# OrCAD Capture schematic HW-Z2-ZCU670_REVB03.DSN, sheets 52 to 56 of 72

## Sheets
52 052 VCC1V8 8A Reg: size Custom
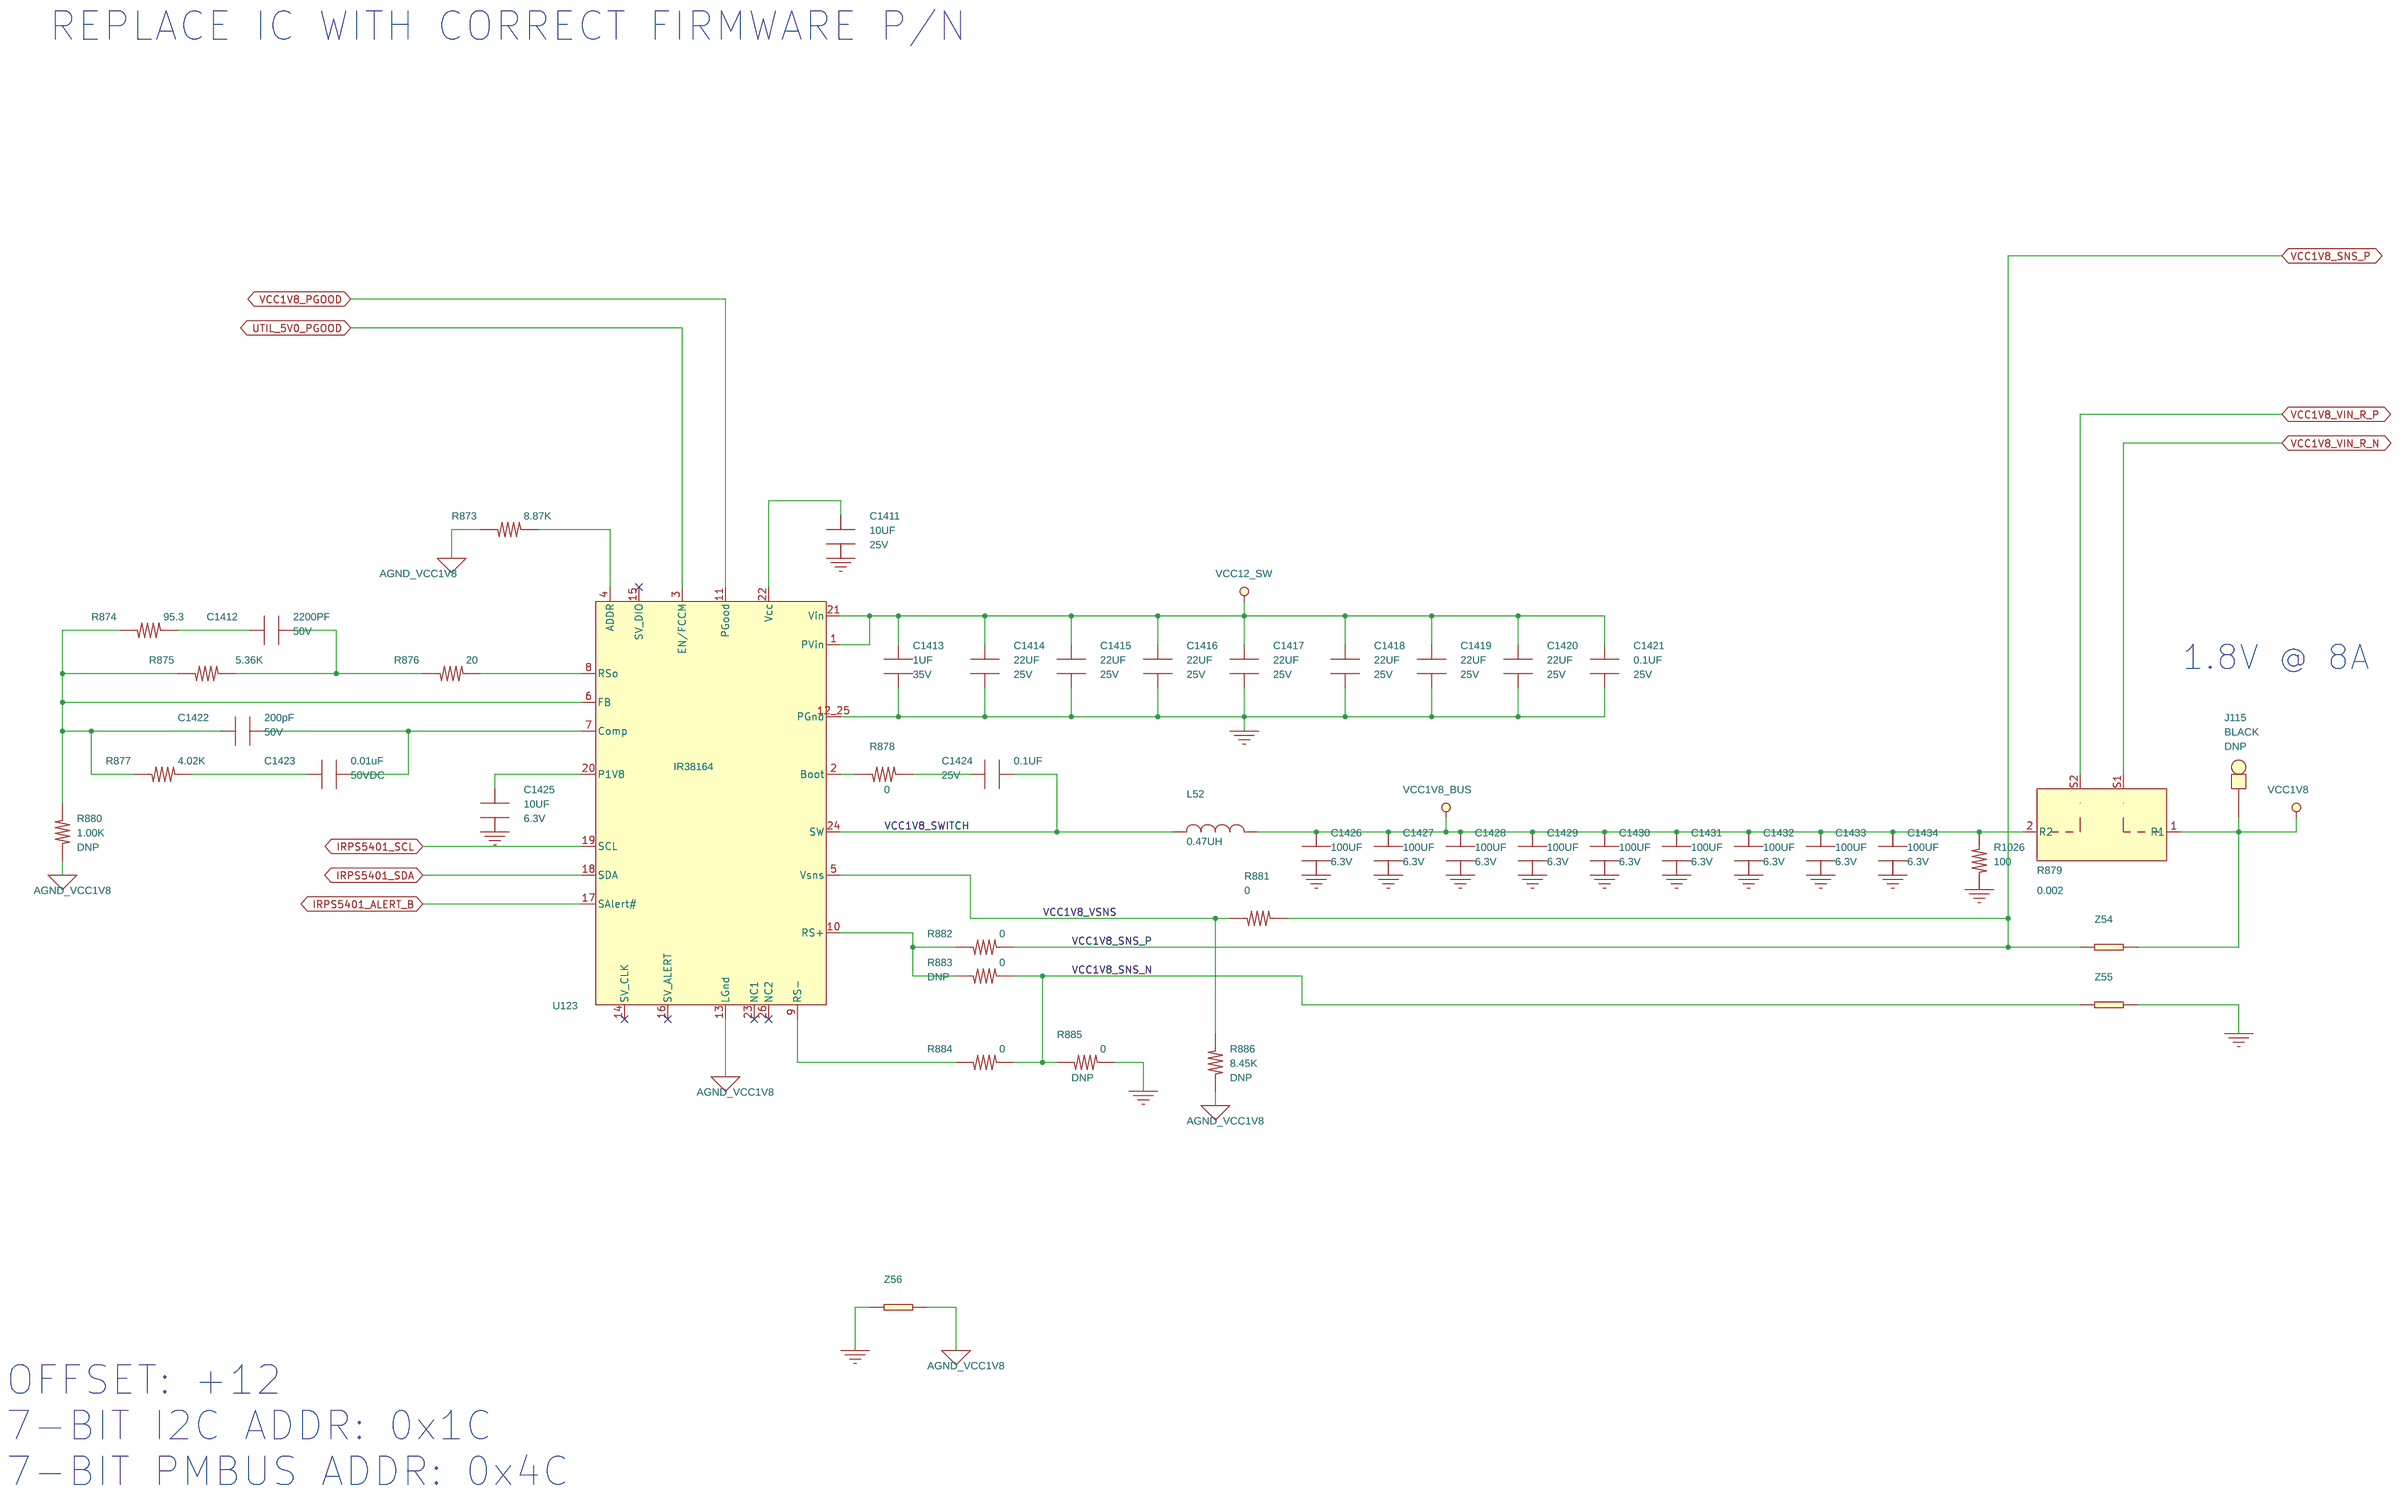
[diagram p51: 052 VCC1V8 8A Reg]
53 053 ADC_AVCC DAC_AVCC Reglators: size Custom
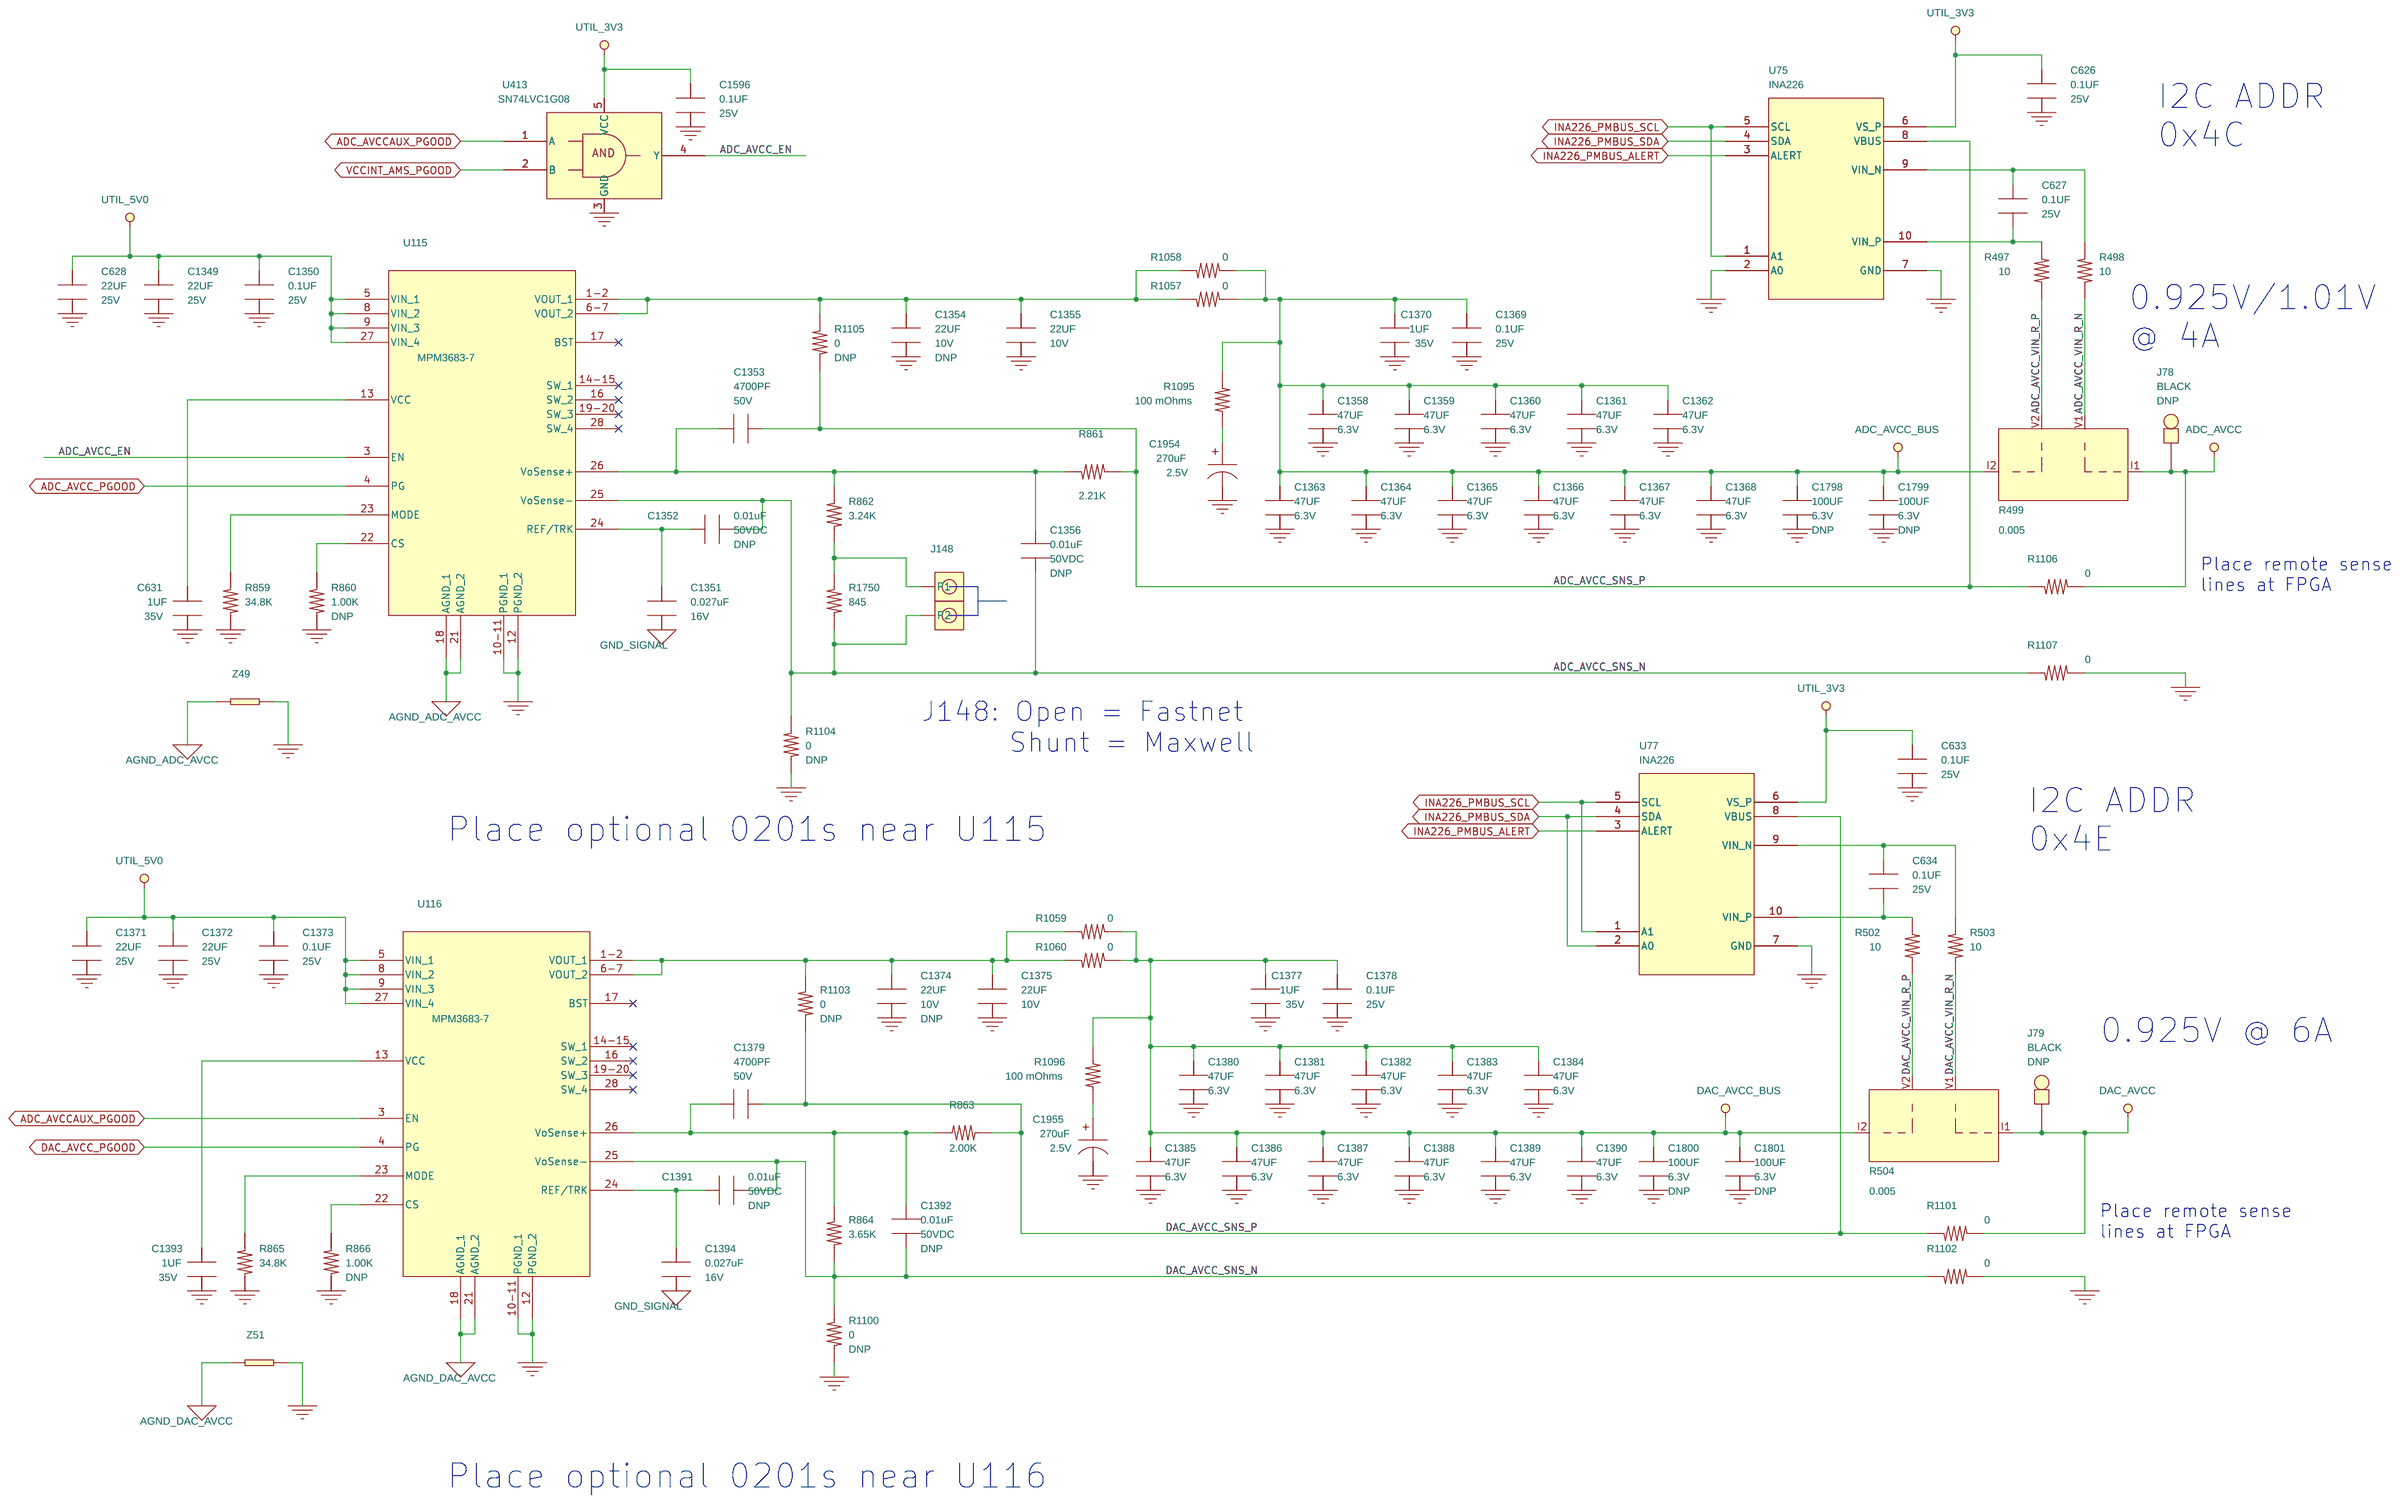
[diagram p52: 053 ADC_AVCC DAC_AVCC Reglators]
54 054 ADC_AVCCAUX 2A Regulator: size Custom
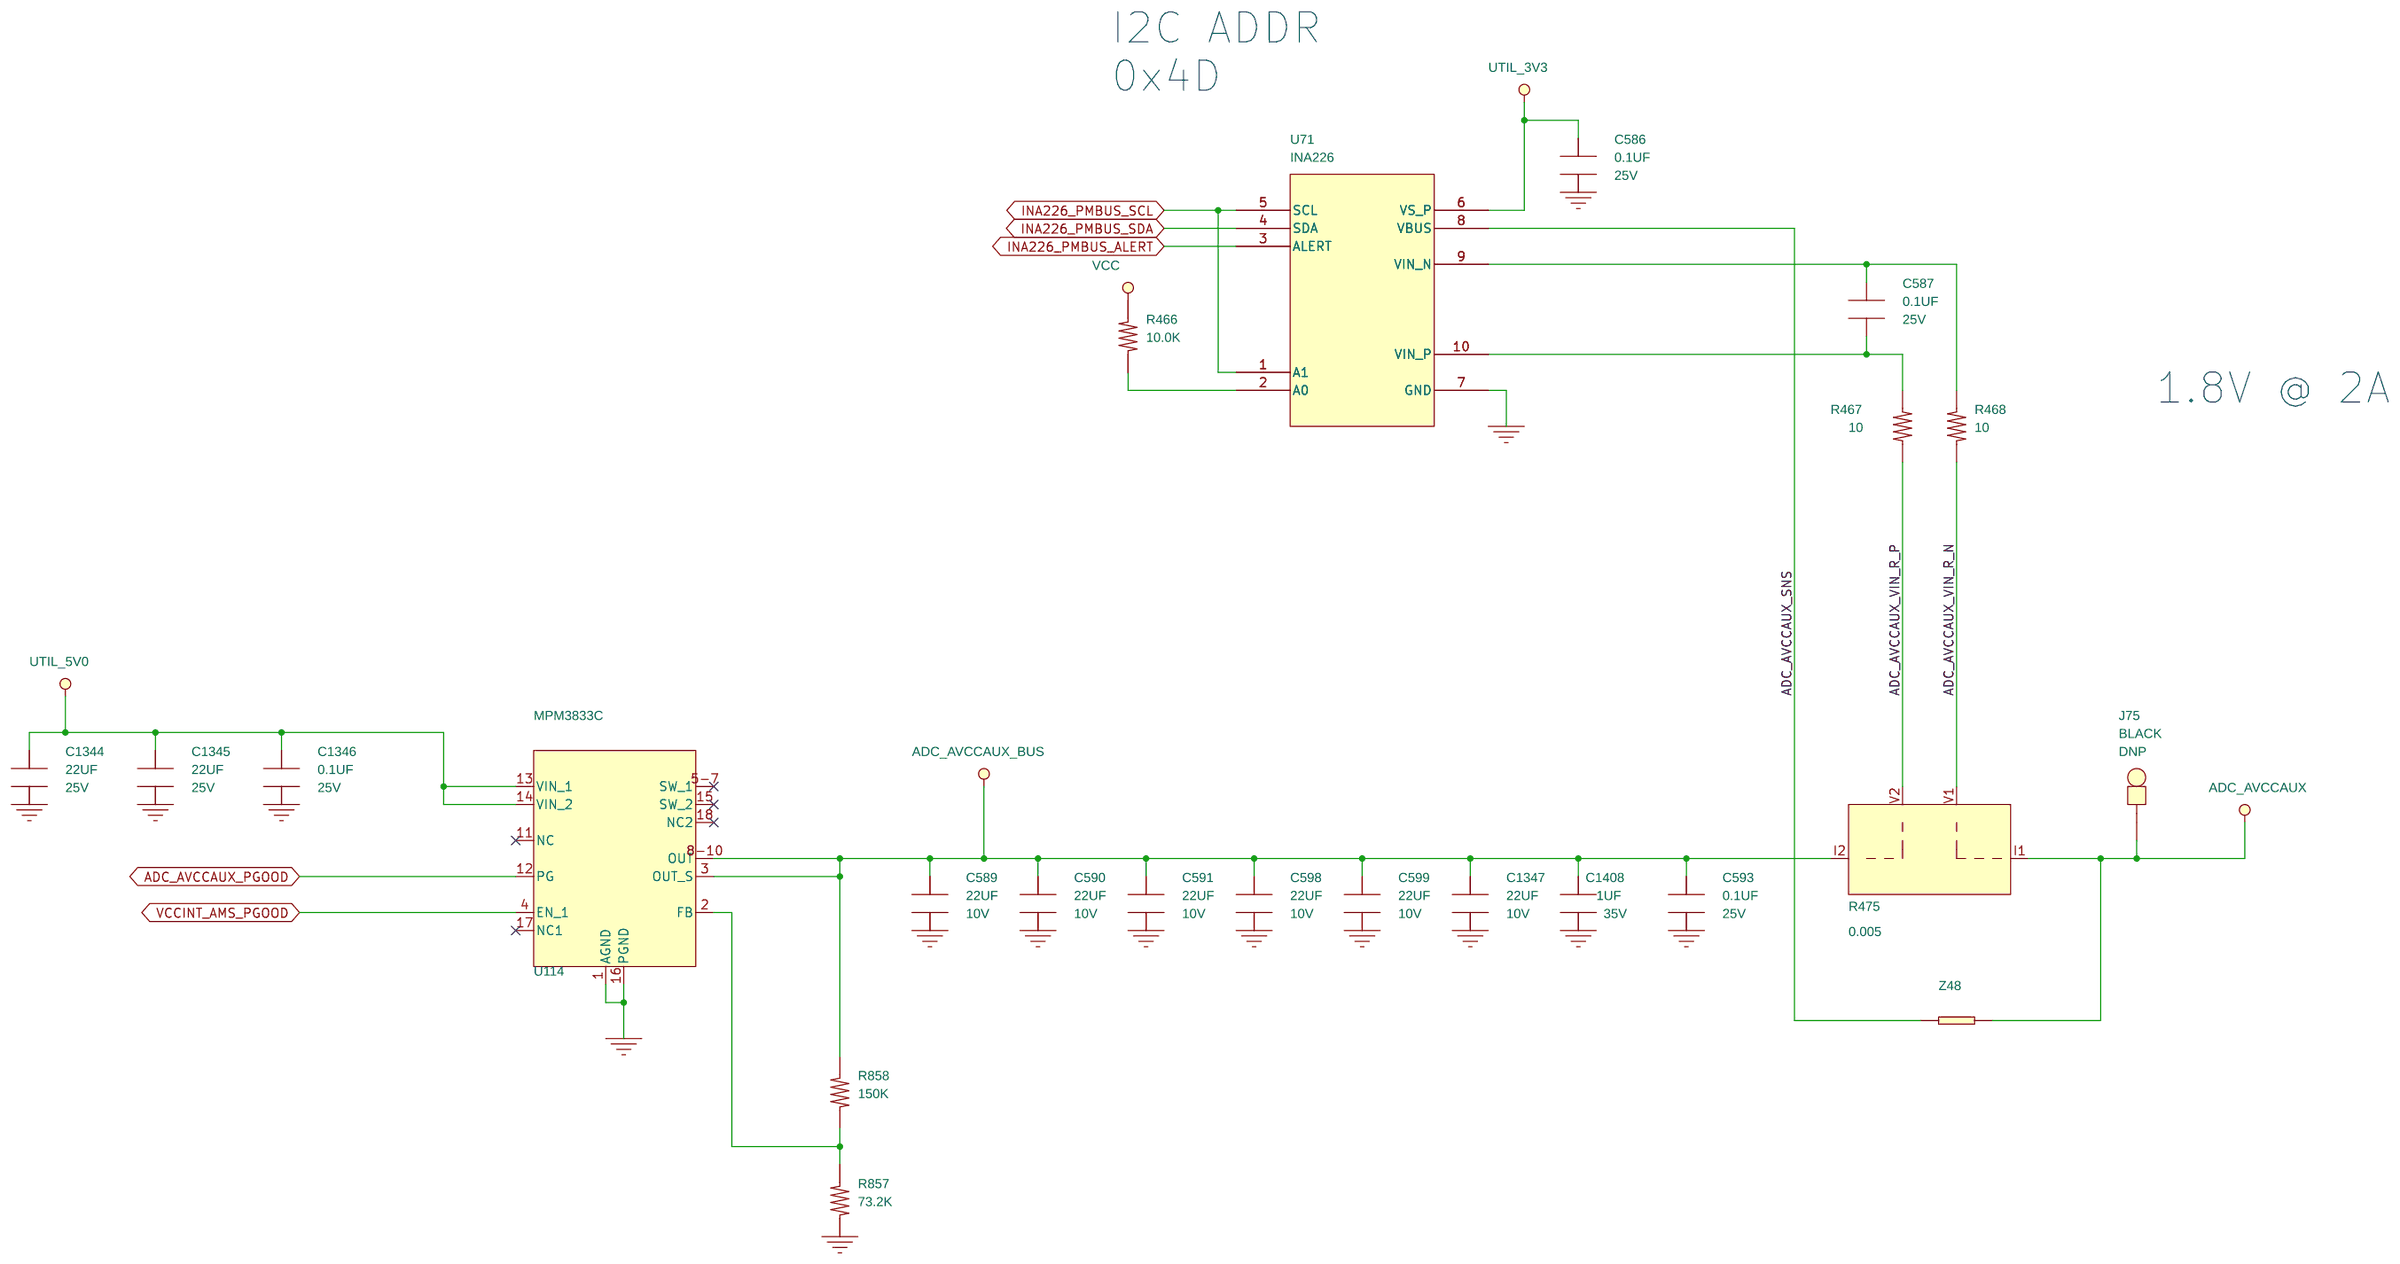
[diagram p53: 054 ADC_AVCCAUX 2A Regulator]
55 055 DAC_AVCCAUX DAC_AVTT Regs: size Custom
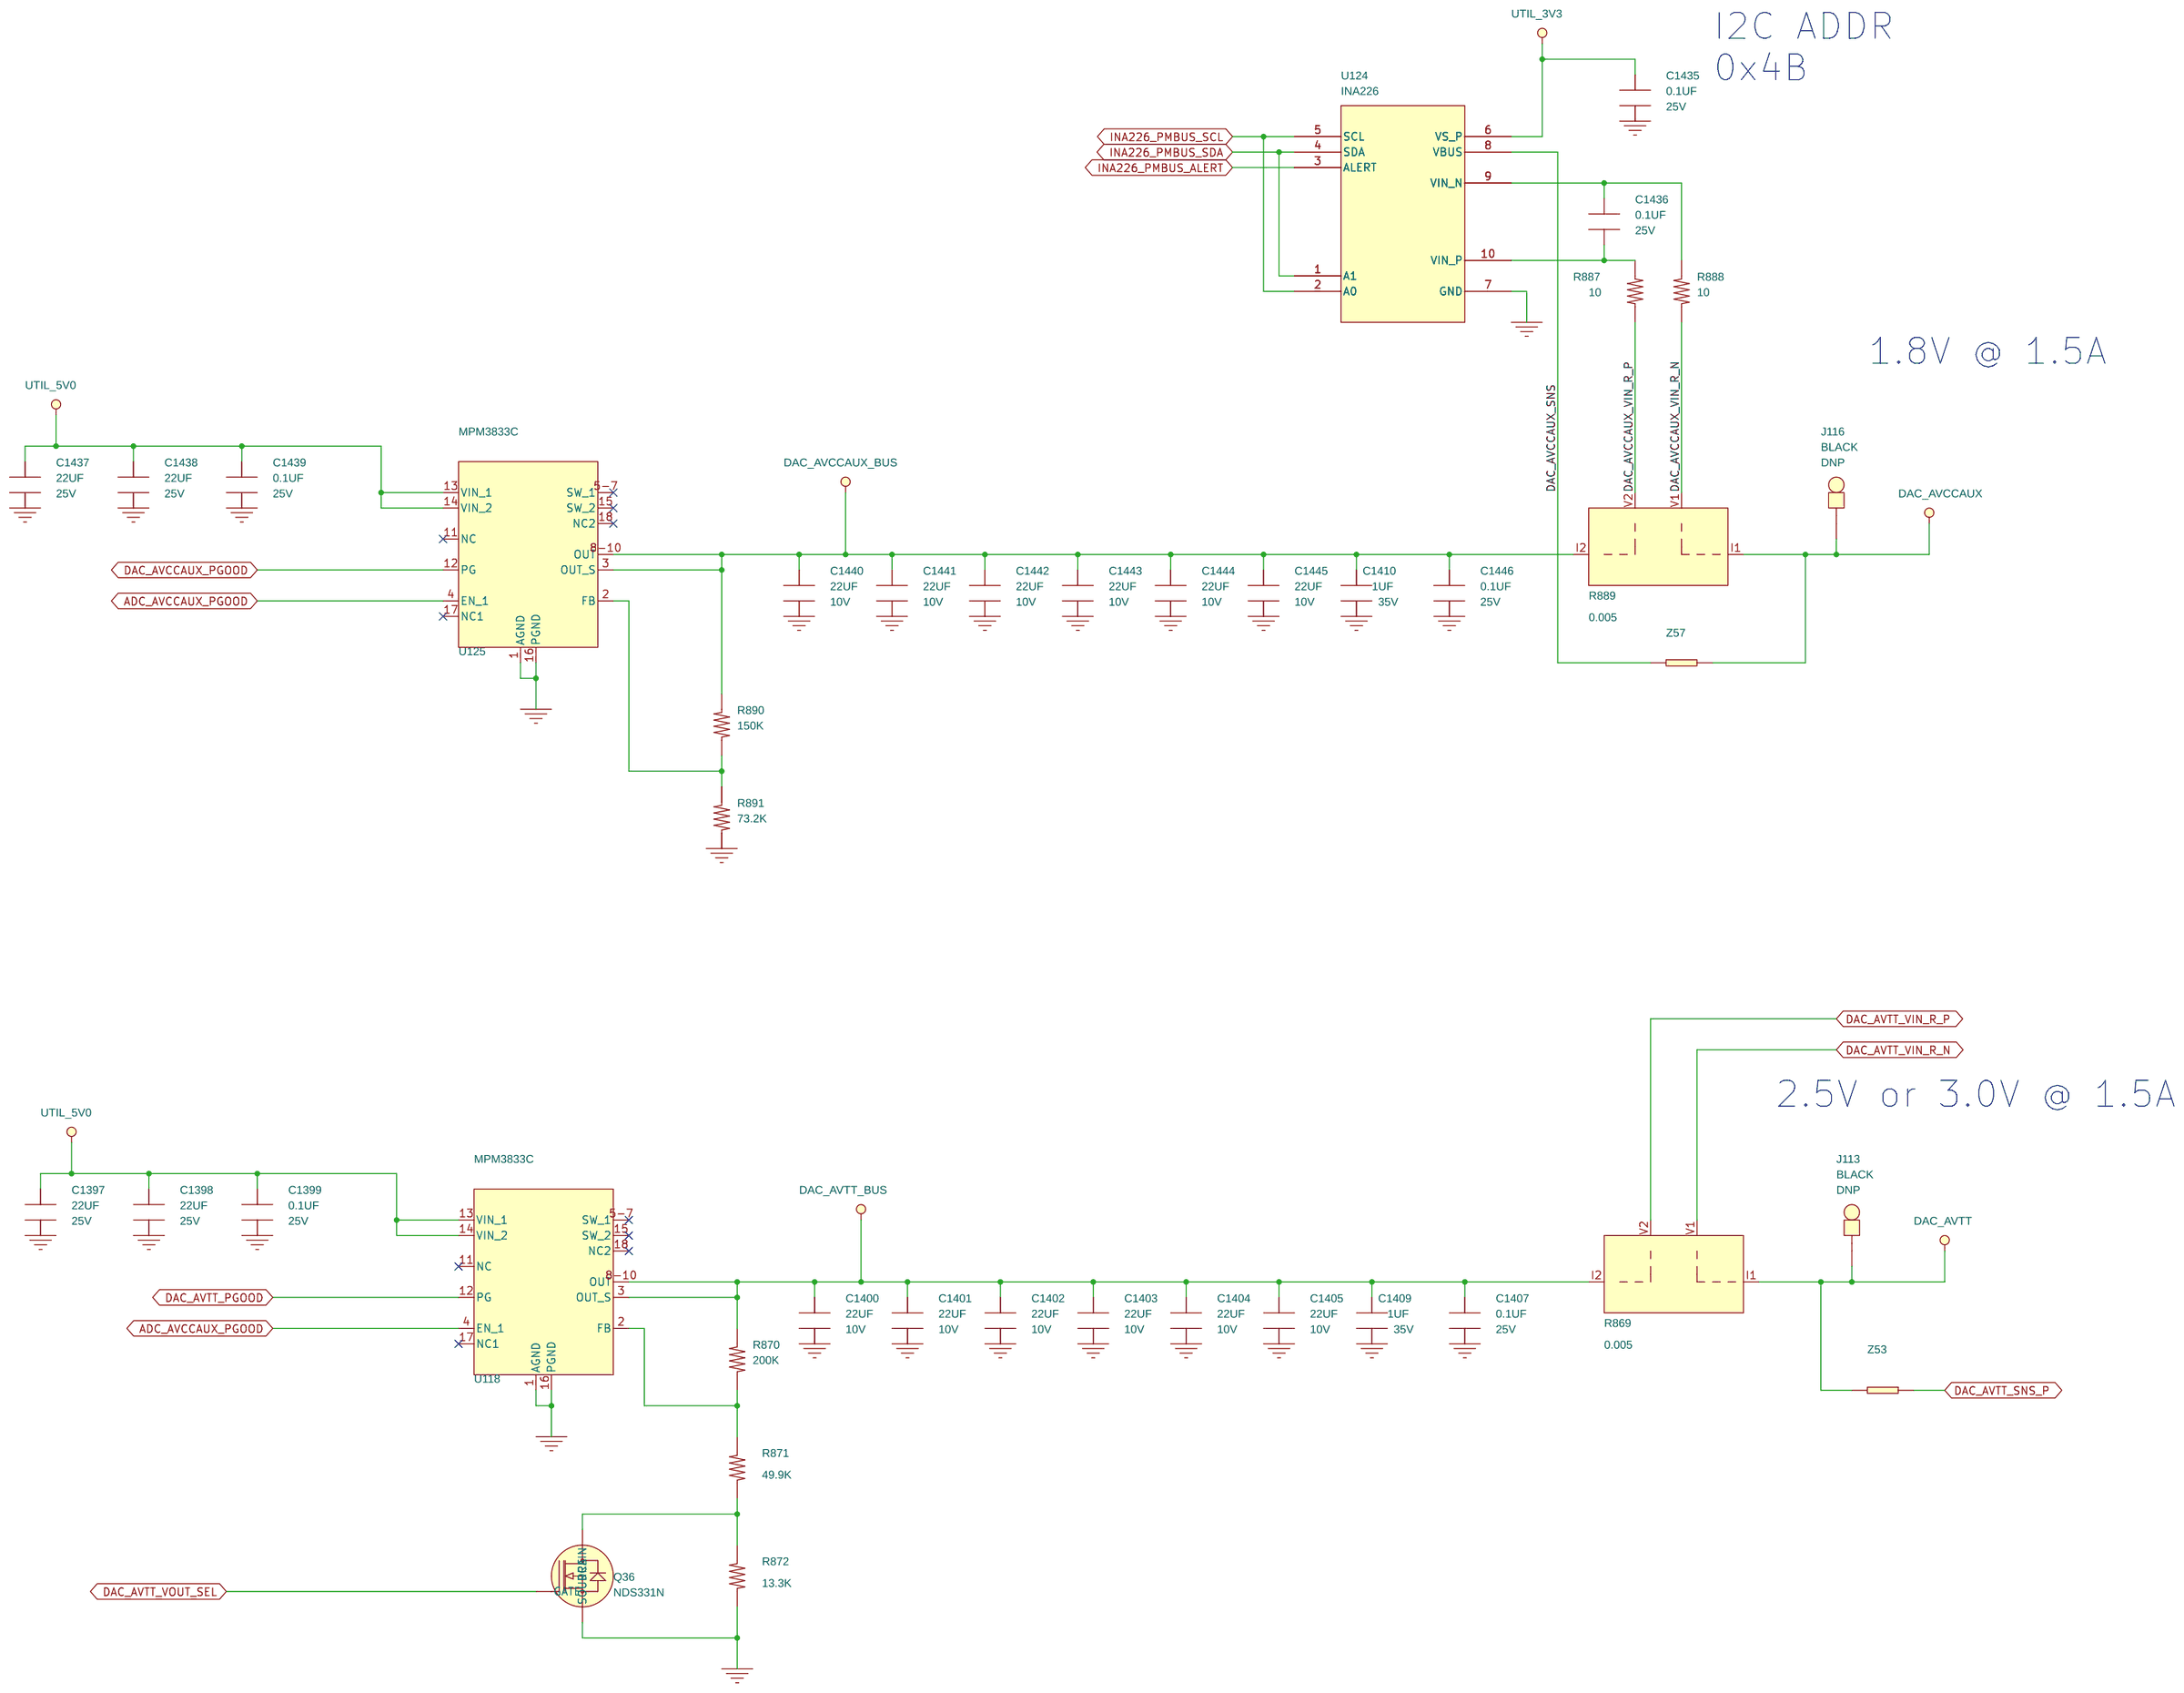
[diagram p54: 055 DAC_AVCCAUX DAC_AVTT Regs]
56 056 PMIC Current Sense: size Custom
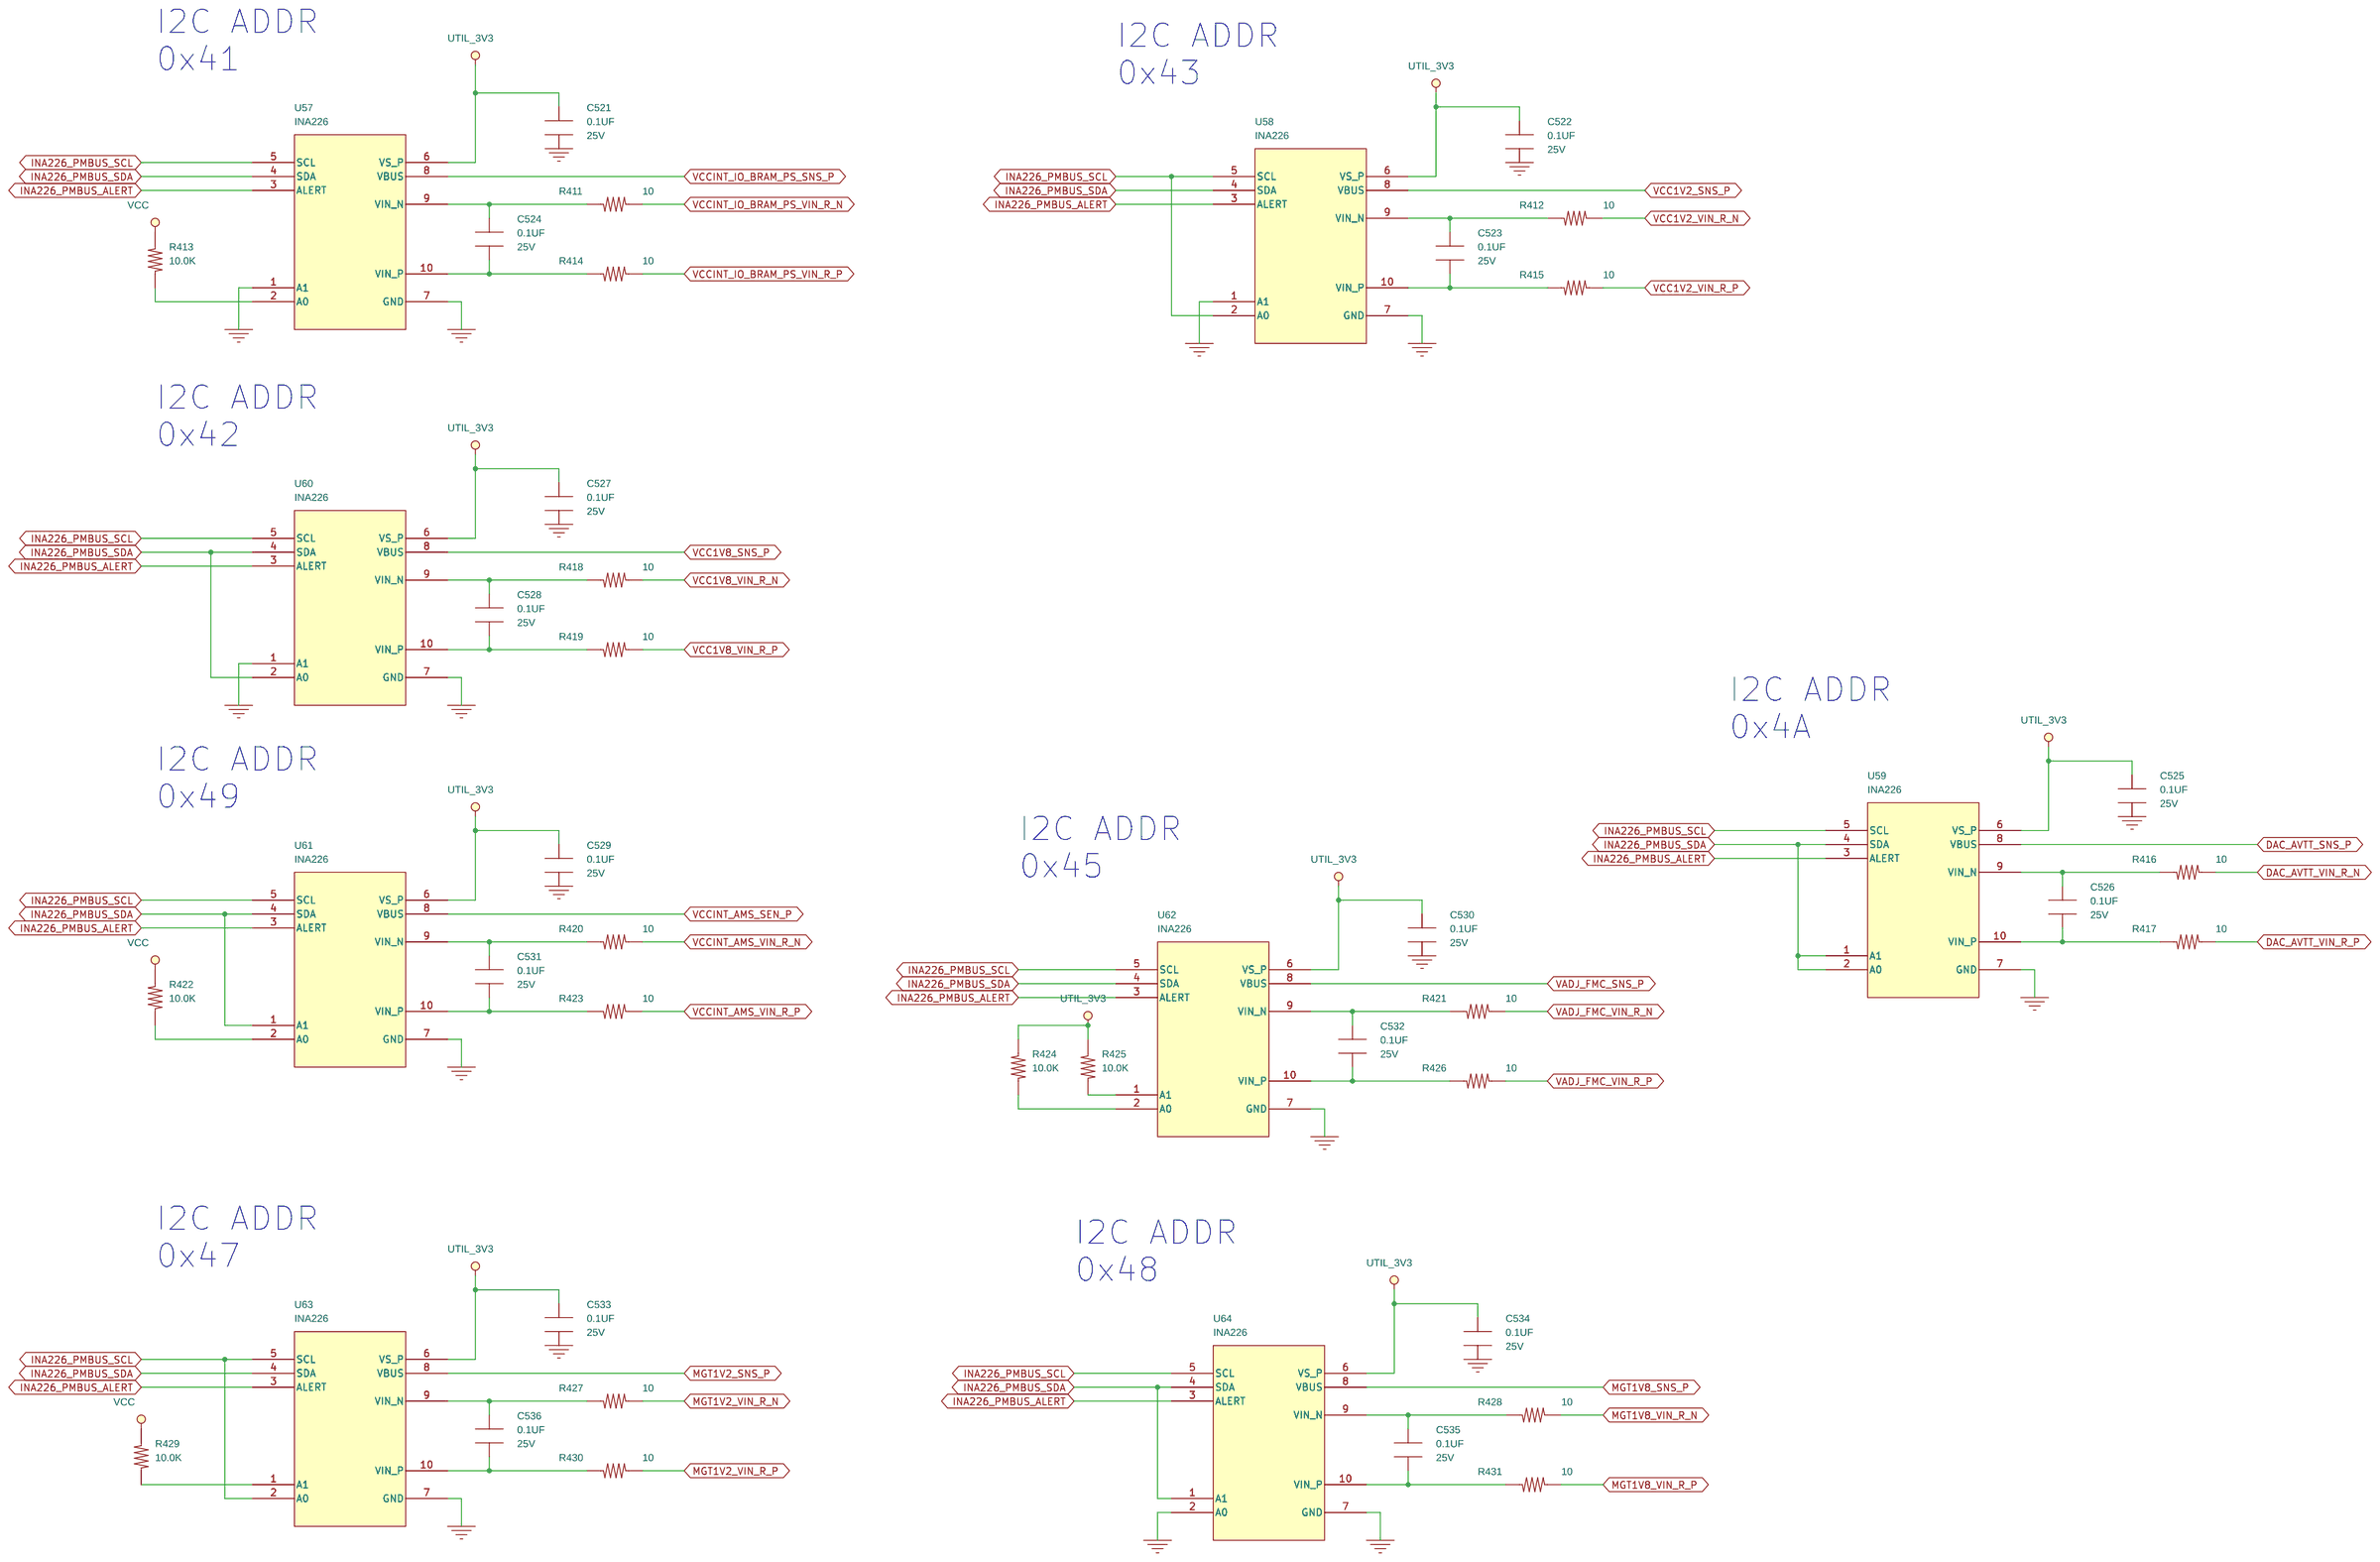
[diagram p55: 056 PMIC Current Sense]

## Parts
sheet 052 VCC1V8 8A Reg
C1411  10UF  [CAPC320X250X220]
C1412  2200PF  [CAPC100X50X55]
C1413  1UF  [CAPC100X50X60]
C1414  22UF  [CAPC320X160X180]
C1415  22UF  [CAPC320X160X180]
C1416  22UF  [CAPC320X160X180]
C1417  22UF  [CAPC320X160X180]
C1418  22UF  [CAPC320X160X180]
C1419  22UF  [CAPC320X160X180]
C1420  22UF  [CAPC320X160X180]
C1421  0.1UF  [CAPC100X50X55]
C1422  200pF  [CAPC100X50X55]
C1423  0.01uF  [CAPC100X50X55]
C1424  0.1UF  [CAPC100X50X55]
C1425  10UF  [CAPC100X50X70]
C1426  100UF  [CAPC320X160X180]
C1427  100UF  [CAPC320X160X180]
C1428  100UF  [CAPC320X160X180]
C1429  100UF  [CAPC320X160X180]
C1430  100UF  [CAPC320X160X180]
C1431  100UF  [CAPC320X160X180]
C1432  100UF  [CAPC320X160X180]
C1433  100UF  [CAPC320X160X180]
C1434  100UF  [CAPC320X160X180]
J115  BLACK  [TP_KEY_MINI]
L52  0.47UH  [INDM6864X300N]
R873  8.87K  [RESC100X50X40]
R874  95.3  [RESC100X50X40]
R875  5.36K  [RESC100X50X40]
R876  20  [RESC100X50X40]
R877  4.02K  [RESC100X50X40]
R878  0  [RESC100X50X40]
R879  0.002  [RES_WSL3637]
R880  1.00K  [RESC100X50X40]
R881  0  [RESC100X50X40]
R882  0  [RESC100X50X40]
R883  0  [RESC100X50X40]
R884  0  [RESC100X50X40]
R885  0  [RESC100X50X40]
R886  8.45K  [RESC100X50X40]
R1026  100  [RESC100X50X40]
U123  IR38164  [QFN_IR38164_26]
Z54  0201_SHORT  [0201_SHORT]
Z55  0201_SHORT  [0201_SHORT]
Z56  0201_SHORT  [0201_SHORT]
sheet 053 ADC_AVCC DAC_AVCC Reglators
C626  0.1UF  [CAPC100X50X55]
C627  0.1UF  [CAPC100X50X55]
C628  22UF  [CAPC320X160X180]
C631  1UF  [CAPC100X50X60]
C633  0.1UF  [CAPC100X50X55]
C634  0.1UF  [CAPC100X50X55]
C1349  22UF  [CAPC320X160X180]
C1350  0.1UF  [CAPC100X50X55]
C1351  0.027uF  [CAPC100X50X55]
C1352  0.01uF  [CAPC100X50X55]
C1353  4700PF  [CAPC100X50X55]
C1354  22UF  [CAPC200X125X145]
C1355  22UF  [CAPC200X125X145]
C1356  0.01uF  [CAPC100X50X55]
C1358  47UF  [CAPC200X125X145]
C1359  47UF  [CAPC200X125X145]
C1360  47UF  [CAPC200X125X145]
C1361  47UF  [CAPC200X125X145]
C1362  47UF  [CAPC200X125X145]
C1363  47UF  [CAPC200X125X145]
C1364  47UF  [CAPC200X125X145]
C1365  47UF  [CAPC200X125X145]
C1366  47UF  [CAPC200X125X145]
C1367  47UF  [CAPC200X125X145]
C1368  47UF  [CAPC200X125X145]
C1369  0.1UF  [CAPC100X50X55]
C1370  1UF  [CAPC100X50X60]
C1371  22UF  [CAPC320X160X180]
C1372  22UF  [CAPC320X160X180]
C1373  0.1UF  [CAPC100X50X55]
C1374  22UF  [CAPC200X125X145]
C1375  22UF  [CAPC200X125X145]
C1377  1UF  [CAPC100X50X60]
C1378  0.1UF  [CAPC100X50X55]
C1379  4700PF  [CAPC100X50X55]
C1380  47UF  [CAPC200X125X145]
C1381  47UF  [CAPC200X125X145]
C1382  47UF  [CAPC200X125X145]
C1383  47UF  [CAPC200X125X145]
C1384  47UF  [CAPC200X125X145]
C1385  47UF  [CAPC200X125X145]
C1386  47UF  [CAPC200X125X145]
C1387  47UF  [CAPC200X125X145]
C1388  47UF  [CAPC200X125X145]
C1389  47UF  [CAPC200X125X145]
C1390  47UF  [CAPC200X125X145]
C1391  0.01uF  [CAPC100X50X55]
C1392  0.01uF  [CAPC100X50X55]
C1393  1UF  [CAPC100X50X60]
C1394  0.027uF  [CAPC100X50X55]
C1596  0.1UF  [CAPC100X50X55]
C1798  100UF  [CAPC320X160X180]
C1799  100UF  [CAPC320X160X180]
C1800  100UF  [CAPC320X160X180]
C1801  100UF  [CAPC320X160X180]
C1954  270uF  [CAPMP350X280X200]
C1955  270uF  [CAPMP350X280X200]
J78  BLACK  [TP_KEY_MINI]
J79  BLACK  [TP_KEY_MINI]
J148  HDR_1X2  [HDR_1X2]
R497  10  [RESC100X50X40]
R498  10  [RESC100X50X40]
R499  0.005  [1224_SMT]
R502  10  [RESC100X50X40]
R503  10  [RESC100X50X40]
R504  0.005  [1224_SMT]
R859  34.8K  [RESC100X50X40]
R860  1.00K  [RESC100X50X40]
R861  2.21K  [RESC100X50X40]
R862  3.24K  [RESC100X50X40]
R863  2.00K  [RESC100X50X40]
R864  3.65K  [RESC100X50X40]
R865  34.8K  [RESC100X50X40]
R866  1.00K  [RESC100X50X40]
R1057  0  [INDP200X160X120]
R1058  0  [INDP200X160X120]
R1059  0  [INDP200X160X120]
R1060  0  [INDP200X160X120]
R1095  100 mOhms  [RES_WSL0805]
R1096  100 mOhms  [RES_WSL0805]
R1100  0  [RESC60X30X26]
R1101  0  [RESC60X30X26]
R1102  0  [RESC60X30X26]
R1103  0  [RESC60X30X26]
R1104  0  [RESC60X30X26]
R1105  0  [RESC60X30X26]
R1106  0  [RESC60X30X26]
R1107  0  [RESC60X30X26]
R1750  845  [RESC100X50X40]
U75  INA226  [DGS_MSOP_10]
U77  INA226  [DGS_MSOP_10]
U115  MPM3683-7  [QFN_MPM3683_28]
U116  MPM3683-7  [QFN_MPM3683_28]
U413  SN74LVC1G08  [SC70_5]
Z49  0201_SHORT  [0201_SHORT]
Z51  0201_SHORT  [0201_SHORT]
sheet 054 ADC_AVCCAUX 2A Regulator
C586  0.1UF  [CAPC100X50X55]
C587  0.1UF  [CAPC100X50X55]
C589  22UF  [CAPC200X125X145]
C590  22UF  [CAPC200X125X145]
C591  22UF  [CAPC200X125X145]
C593  0.1UF  [CAPC100X50X55]
C598  22UF  [CAPC200X125X145]
C599  22UF  [CAPC200X125X145]
C1344  22UF  [CAPC320X160X180]
C1345  22UF  [CAPC320X160X180]
C1346  0.1UF  [CAPC100X50X55]
C1347  22UF  [CAPC200X125X145]
C1408  1UF  [CAPC100X50X60]
J75  BLACK  [TP_KEY_MINI]
R466  10.0K  [RESC100X50X40]
R467  10  [RESC100X50X40]
R468  10  [RESC100X50X40]
R475  0.005  [1224_SMT]
R857  73.2K  [RESC100X50X40]
R858  150K  [RESC100X50X40]
U71  INA226  [DGS_MSOP_10]
U114  MPM3833C  [QFN_MPM3833_18]
Z48  0201_SHORT  [0201_SHORT]
sheet 055 DAC_AVCCAUX DAC_AVTT Regs
C1397  22UF  [CAPC320X160X180]
C1398  22UF  [CAPC320X160X180]
C1399  0.1UF  [CAPC100X50X55]
C1400  22UF  [CAPC200X125X145]
C1401  22UF  [CAPC200X125X145]
C1402  22UF  [CAPC200X125X145]
C1403  22UF  [CAPC200X125X145]
C1404  22UF  [CAPC200X125X145]
C1405  22UF  [CAPC200X125X145]
C1407  0.1UF  [CAPC100X50X55]
C1409  1UF  [CAPC100X50X60]
C1410  1UF  [CAPC100X50X60]
C1435  0.1UF  [CAPC100X50X55]
C1436  0.1UF  [CAPC100X50X55]
C1437  22UF  [CAPC320X160X180]
C1438  22UF  [CAPC320X160X180]
C1439  0.1UF  [CAPC100X50X55]
C1440  22UF  [CAPC200X125X145]
C1441  22UF  [CAPC200X125X145]
C1442  22UF  [CAPC200X125X145]
C1443  22UF  [CAPC200X125X145]
C1444  22UF  [CAPC200X125X145]
C1445  22UF  [CAPC200X125X145]
C1446  0.1UF  [CAPC100X50X55]
J113  BLACK  [TP_KEY_MINI]
J116  BLACK  [TP_KEY_MINI]
Q36  NDS331N  [SOT_23]
R869  0.005  [1224_SMT]
R870  200K  [RESC100X50X40]
R871  49.9K  [RESC100X50X40]
R872  13.3K  [RESC100X50X40]
R887  10  [RESC100X50X40]
R888  10  [RESC100X50X40]
R889  0.005  [1224_SMT]
R890  150K  [RESC100X50X40]
R891  73.2K  [RESC100X50X40]
U118  MPM3833C  [QFN_MPM3833_18]
U124  INA226  [DGS_MSOP_10]
U125  MPM3833C  [QFN_MPM3833_18]
Z53  0201_SHORT  [0201_SHORT]
Z57  0201_SHORT  [0201_SHORT]
sheet 056 PMIC Current Sense
C521  0.1UF  [CAPC100X50X55]
C522  0.1UF  [CAPC100X50X55]
C523  0.1UF  [CAPC100X50X55]
C524  0.1UF  [CAPC100X50X55]
C525  0.1UF  [CAPC100X50X55]
C526  0.1UF  [CAPC100X50X55]
C527  0.1UF  [CAPC100X50X55]
C528  0.1UF  [CAPC100X50X55]
C529  0.1UF  [CAPC100X50X55]
C530  0.1UF  [CAPC100X50X55]
C531  0.1UF  [CAPC100X50X55]
C532  0.1UF  [CAPC100X50X55]
C533  0.1UF  [CAPC100X50X55]
C534  0.1UF  [CAPC100X50X55]
C535  0.1UF  [CAPC100X50X55]
C536  0.1UF  [CAPC100X50X55]
R411  10  [RESC100X50X40]
R412  10  [RESC100X50X40]
R413  10.0K  [RESC100X50X40]
R414  10  [RESC100X50X40]
R415  10  [RESC100X50X40]
R416  10  [RESC100X50X40]
R417  10  [RESC100X50X40]
R418  10  [RESC100X50X40]
R419  10  [RESC100X50X40]
R420  10  [RESC100X50X40]
R421  10  [RESC100X50X40]
R422  10.0K  [RESC100X50X40]
R423  10  [RESC100X50X40]
R424  10.0K  [RESC100X50X40]
R425  10.0K  [RESC100X50X40]
R426  10  [RESC100X50X40]
R427  10  [RESC100X50X40]
R428  10  [RESC100X50X40]
R429  10.0K  [RESC100X50X40]
R430  10  [RESC100X50X40]
R431  10  [RESC100X50X40]
U57  INA226  [DGS_MSOP_10]
U58  INA226  [DGS_MSOP_10]
U59  INA226  [DGS_MSOP_10]
U60  INA226  [DGS_MSOP_10]
U61  INA226  [DGS_MSOP_10]
U62  INA226  [DGS_MSOP_10]
U63  INA226  [DGS_MSOP_10]
U64  INA226  [DGS_MSOP_10]

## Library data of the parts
C1411 = CAP_NP: Cap Cer 10uF 10% 25V X5R 1210; ALT_SYMBOLS: CAPC320X250X220RND; Agile Part Number: CAP-00113-01; CIP Link: http://xsjbrdwin1/CIP-E/Component/Index/All?pn=100123; Dielectric Type: X5R; OWNER: 3709; PRICE: 0.18; Part Type: CERAMIC; PartType: CERAMIC; ROHS: Yes; Tolerance: 10%; Voltage: 25V; barcode: 100123
C1412 = CAP_NP: Cap Cer 2.2nF 10% 50V X7R 0402; ALT_SYMBOLS: CAPC100X50X55RND; Agile Part Number: CAP-00030-01; Barcode: 100095; CIP Link: http://xsjbrdwin1/CIP-E/Component/Index/All?pn=100095; Dielectric Type: X7R; Part Type: CERAMIC; Tolerance: 10%; Voltage: 50V
C631 C1370 C1377 C1393 C1408-C1410 C1413 = CAP_NP: Cap Cer 1uF 10% 35V X5R 0402; ALT_SYMBOLS: CAPC100X50X60RND; Agile Part Number: CAP-00165-01; CIP Link: http://xsjbrdwin1/CIP-E/Component/Index/All?pn=100192; Dielectric Type: X5R; OWNER: 3709; PRICE: 0.04; Part Type: CERAMIC; PartType: CERAMIC; ROHS: Yes; Tolerance: 10%; Voltage: 35V; barcode: 100192
C628 C1344 C1345 C1349 C1371 C1372 C1397 C1398 C1414-C1420 C1437 C1438 = CAP_NP: Cap Cer 22uF 10% 25V X5R 1206; ALT_SYMBOLS: CAPC320X160X180RND; Agile Part Number: CAP-00058-01; CIP Link: http://xsjbrdwin1/CIP-E/Component/Index/All?pn=100026; Dielectric Type: X5R; OWNER: 3709; PRICE: 0.17; Part Type: CERAMIC; PartType: CERAMIC; ROHS: Yes; Tolerance: 10%; Voltage: 25V; barcode: 100026
C521-C536 C586 C587 C593 C626 C627 C633 C634 C1346 C1350 C1369 C1373 C1378 C1399 C1407 C1421 C1424 C1435 C1436 C1439 C1446 C1596 = CAP_NP: Cap Cer 100nF 10% 25V X5R 0402; ALT_SYMBOLS: CAPC100X50X55RND; Agile Part Number: CAP-00068-01; CIP Link: http://xsjbrdwin1/CIP-E/Component/Index/All?pn=100040; Dielectric Type: X5R; OWNER: 4001; PRICE: 0.01; Part Type: CERAMIC; PartType: CERAMIC; ROHS: Yes; Tolerance: 10%; Voltage: 25V; barcode: 100040
C1422 = CAP_NP: Cap Cer 200pF 5% 50V C0G 0402; Agile Part Number: CAP-00272-01; Barcode: 10000006; CIP Link: http://xsjbrdwin1/CIP-E/Component/Index/All?pn=10000006; Part Type: --\-\0402 (1005 Metric); Tolerance: 2%; Voltage: 50V
C1423 = CAP_NP: Cap Cer 10nF 10% 50V X7R 0402; ALT_SYMBOLS: CAPC100X50X55RND; Agile Part Number: CAP-00031-01; CIP Link: http://xsjbrdwin1/CIP-E/Component/Index/All?pn=100003; Dielectric Type: X7R; OWNER: 4001; PRICE: 0; Part Type: CERAMIC; PartType: CERAMIC; ROHS: Yes; Tolerance: 10%; Voltage: 50VDC; barcode: 100003
C1425 = CAP_NP: Cap Cer 10uF 20%  6.3V X6S 0402; ALT_SYMBOLS: CAPC100X50X55RND; Agile Part Number: CAP-00035-01; CIP Link: http://xsjbrdwin1/CIP-E/Component/Index/All?pn=100268; Dielectric Type: X6S; OWNER: 6176; PRICE: 0.06; Part Type: CERAMIC; PartType: CERAMIC; ROHS: Yes; Tolerance: 20%; Voltage: 6.3V; barcode: 100268
C1426-C1434 = CAP_NP: Cap Cer 100uF 20% 6.3V X5R 1206; ALT_SYMBOLS: 1206; Agile Part Number: CAP-00061-01; CIP Link: http://xsjbrdwin1/CIP-E/Component/Index/All?pn=100029; Dielectric Type: X5R; OWNER: 3709; PRICE: 0.17; Part Type: CERAMIC; PartType: CERAMIC; ROHS: Yes; Tolerance: 20%; Voltage: 6.3V; barcode: 100029
J75 J78 J79 J113 J115 J116 = TP-HOOK: Conn Test Point Mini Loop Black TH; ALT_SYMBOLS: TP_KEY_MINI_DNP; ASSEMBLY_OPTIONS: DNP; Agile Part Number: CON-00272-01; Barcode: 900015; CIP Link: http://xsjbrdwin1/CIP-E/Component/Index/All?pn=900015; OWNER: 3709; Part Type: TEST POINT; PartType: TEST POINT; Pins: 1PIN; Pitch: 0.04IN; ROHS: Yes
L52 = IND: Ind 470nH 20% 17.5A Irms 26A Isat 4.2mR 6.47x6.47mm SMT Shielded; Agile Part Number: IND-00094-01; Barcode: 300183; CIP Link: http://xsjbrdwin1/CIP-E/Component/Index/All?pn=300183; OWNER: 3709; PRICE: 0.5; Part Type: POWER INDUCTOR; PartType: POWER INDUCTOR; ROHS: YES; Tolerance: 0.2
R873 = RES: Res 8K87 1% 1/16W 100PPM 50V 0402; Agile Part Number: RES-00265-01; Barcode: 200286; CIP Link: http://xsjbrdwin1/CIP-E/Component/Index/All?pn=200286; Part Type: SMT - 1%; Rated Power: 1/16W; Tolerance: 1%
R874 = RES: Res 95R3 1% 1/16W 100PPM 50V 0402; Agile Part Number: RES-00472-01; Barcode: 200573; CIP Link: http://xsjbrdwin1/CIP-E/Component/Index/All?pn=200573; Part Type: SMT - 1%; Rated Power: 1/16W; Tolerance: 1%
R875 = RES: Res 5K36 1% 1/16W 100PPM 50V 0402; ALT_SYMBOLS: RESC100X50X40RND; Agile Part Number: RES-00422-01; Barcode: 200489; CIP Link: http://xsjbrdwin1/CIP-E/Component/Index/All?pn=200489; Part Type: SMT - 1%; Rated Power: 1/16W; Tolerance: 1%
R876 = RES: Res 20R 1% 1/16W 100PPM 50V 0402; ALT_SYMBOLS: RESC100X50X40RND; Agile Part Number: RES-00033-01; Barcode: 200119; CIP Link: http://xsjbrdwin1/CIP-E/Component/Index/All?pn=200119; Part Type: SMT - 1%; Rated Power: 1/16W; Tolerance: 1%
R877 = RES: RES SMD 4.02K OHM 1% 1/10W 0402; ALT_SYMBOLS: RESC100X50X40RND; Agile Part Number: RES-00098-01; Barcode: 200062; CIP Link: http://xsjbrdwin1/CIP-E/Component/Index/All?pn=200062; Part Type: SMT - 1%; Rated Power: 1/10W; Tolerance: 1%
R878 = RES: Res 0R 50mR 1A 0402; ALT_SYMBOLS: RESC100X50X40RND; Agile Part Number: RES-00010-01; Barcode: 200012; CIP Link: http://xsjbrdwin1/CIP-E/Component/Index/All?pn=200012; OWNER: 4001; PRICE: 0.01; Part Type: SMT - 5%; PartType: SMT - 5%; Power: 1/10W; ROHS: Yes; Tolerance: 5%; primarykey: 13
R879 = RES_VISHAY_WSL: Res 2mR 1% 3W 75PPM 3637 4-Term; Agile Part Number: RES-00225-01; Barcode: 200240; CIP Link: http://xsjbrdwin1/CIP-E/Component/Index/All?pn=200240; OWNER: 3709; PRICE: 0.84; Part Type: SMT -CURSNS; PartType: SMT -CURSNS; Power: 3W; ROHS: Yes; Rated Power: 3W; Tolerance: 1%; primarykey: 95
R860 R866 R880 = RES: Res 1K 1% 1/16W 100PPM 50V 0402; ALT_SYMBOLS: RESC100X50X40RND; ASSEMBLY_OPTIONS: DNP; Agile Part Number: RES-00027-01; Barcode: 200098; CIP Link: http://xsjbrdwin1/CIP-E/Component/Index/All?pn=200098; Part Type: SMT - 1%; Rated Power: 1/16W; Tolerance: 1%
R881 R882 R884 = RES: Res 0R 50mR 1A 0402; ALT_SYMBOLS: RESC100X50X40RND; Agile Part Number: RES-00010-01; Barcode: 200012; CIP Link: http://xsjbrdwin1/CIP-E/Component/Index/All?pn=200012; OWNER: 3709; Part Type: SMT - 5%; PartType: SMT - 1%; Power: 1/10W; ROHS: Yes; Tolerance: 5%; primarykey: 144
R883 R885 = RES: Res 0R 50mR 1A 0402; ALT_SYMBOLS: RESC100X50X40RND; ASSEMBLY_OPTIONS: DNP; Agile Part Number: RES-00010-01; Barcode: 200012; CIP Link: http://xsjbrdwin1/CIP-E/Component/Index/All?pn=200012; OWNER: 3709; Part Type: SMT - 5%; PartType: SMT - 1%; Power: 1/10W; ROHS: Yes; Tolerance: 5%; primarykey: 144
R886 = RES: RES SMD 8.45K OHM 1% 1/10W 0402; ASSEMBLY_OPTIONS: DNP; Agile Part Number: RES-00423-01; Barcode: 200490; CIP Link: http://xsjbrdwin1/CIP-E/Component/Index/All?pn=200490; OWNER: 3709; PRICE: 0; Part Type: SMT - 1%; PartType: SMT - 1%; Power: 1/10W; ROHS: Yes; Rated Power: 1/10W; Tolerance: 1%; primarykey: 442
R1026 = RES: Res 100R 1% 1/16W 100PPM 50V 0402; ALT_SYMBOLS: RESC100X50X40RND; Agile Part Number: RES-00046-01; Barcode: 200024; CIP Link: http://xsjbrdwin1/CIP-E/Component/Index/All?pn=200024; Part Type: SMT - 1%; Rated Power: 1/16W; Tolerance: 1%
U123 = IR38164: IC V. Reg Step-Down DC/DC Synch 16V 30A 1.5MHz PQFN-24; Agile Part Number: ICS-00507-01; Barcode: 50000035; CIP Link: http://xsjbrdwin1/CIP-E/Component/Index/All?pn=50000035; Part Type: Integrated Circuits (ICs)\--
Z48 Z49 Z51 Z53-Z57 = 0201_SHORT: PCB only 0201_SHORT; ASSEMBLY_OPTIONS: DNP; Barcode: 96000001; CIP Link: http://xsjbrdwin1/CIP-E/Component/Index/All?pn=96000001; OWNER: 3670; Part Type: PCB LAYOUT; PartType: PCB LAYOUT; ROHS: 0
C1351 C1394 = CAP_NP: Cap Cer 27nF 10% 16V X7R 0402; Agile Part Number: CAP-00273-01; Barcode: 10000007; CIP Link: http://xsjbrdwin1/CIP-E/Component/Index/All?pn=10000007; Part Type: CERAMIC; Tolerance: 10%; Voltage: 16V
C1352 C1356 C1391 C1392 = CAP_NP: Cap Cer 10nF 10% 50V X7R 0402; ALT_SYMBOLS: CAPC100X50X55RND; ASSEMBLY_OPTIONS: DNP; Agile Part Number: CAP-00031-01; CIP Link: http://xsjbrdwin1/CIP-E/Component/Index/All?pn=100003; Dielectric Type: X7R; OWNER: 4001; PRICE: 0.01; Part Type: CERAMIC; PartType: CERAMIC; ROHS: Yes; Tolerance: 10%; Voltage: 50VDC; barcode: 100003
C1353 C1379 = CAP_NP: Cap Cer 4.7nF 10% 50V X7R 0402; ALT_SYMBOLS: CAPC100X50X55RND; Agile Part Number: CAP-00139-01; Barcode: 100155; CIP Link: http://xsjbrdwin1/CIP-E/Component/Index/All?pn=100155; Dielectric Type: X7R; Part Type: CERAMIC; Tolerance: 10%; Voltage: 50V
C1354 C1374 = CAP_NP: Cap Cer 22uF 20% 10V X6S 0805; ASSEMBLY_OPTIONS: DNP; Agile Part Number: CAP-00021-01; CIP Link: http://xsjbrdwin1/CIP-E/Component/Index/All?pn=100280; Dielectric Type: X6S; OWNER: 3709; PRICE: 0.17; Part Type: CERAMIC; PartType: CERAMIC; ROHS: Yes; Tolerance: 20%; Voltage: 10V; barcode: 100280
C589-C591 C598 C599 C1347 C1355 C1375 C1400-C1405 C1440-C1445 = CAP_NP: Cap Cer 22uF 20% 10V X6S 0805; Agile Part Number: CAP-00021-01; CIP Link: http://xsjbrdwin1/CIP-E/Component/Index/All?pn=100280; Dielectric Type: X6S; OWNER: 3709; PRICE: 0.17; Part Type: CERAMIC; PartType: CERAMIC; ROHS: Yes; Tolerance: 20%; Voltage: 10V; barcode: 100280
C1358-C1368 C1380-C1390 = CAP_NP: Cap Cer 47uF 20% 6.3V X5R 0805; Agile Part Number: CAP-00046-01; CIP Link: http://xsjbrdwin1/CIP-E/Component/Index/All?pn=100005; Dielectric Type: X5R; OWNER: 3709; PRICE: 0.28; Part Type: CERAMIC; PartType: CERAMIC; ROHS: Yes; Tolerance: 20%; Voltage: 6.3V; barcode: 100005
C1798-C1801 = CAP_NP: Cap Cer 100uF 20% 6.3V X5R 1206; ALT_SYMBOLS: 1206; ASSEMBLY_OPTIONS: DNP; Agile Part Number: CAP-00061-01; CIP Link: http://xsjbrdwin1/CIP-E/Component/Index/All?pn=100029; Dielectric Type: X5R; OWNER: 3709; PRICE: 0.35; Part Type: CERAMIC; PartType: CERAMIC; ROHS: Yes; Tolerance: 20%; Voltage: 6.3V; barcode: 100029
C1954 C1955 = CAP_P: Cap Tant 270uF 20% 2.5V 6mR 3528 SMT; Agile Part Number: CAP-00279-01; Barcode: 10000015; CIP Link: http://xsjbrdwin1/CIP-E/Component/Index/All?pn=10000015; Equivalent Series Resistance: 6mOhm @ 100kHz; Part Type: Unassigned Part Type; Tolerance: 20%; Voltage: 2.5V
J148 = HDR_1X2: Conn Hdr Male Vert 2 Pos 1x2 2.54mm P Black TH; Agile Part Number: CON-00037-01; Barcode: 390102; CIP Link: http://xsjbrdwin1/CIP-E/Component/Index/All?pn=390102; OWNER: 4001; PRICE: 0.03; Part Type: HEADER; PartType: HEADER; Pins: 2PINS; Pitch: 0.100; ROHS: Yes
R411 R412 R414-R421 R423 R426-R428 R430 R431 R467 R468 R497 R498 R502 R503 R887 R888 = RES: Res 10R 1% 1/16W 100PPM 50V 0402; ALT_SYMBOLS: RESC100X50X40RND; Agile Part Number: RES-00025-01; Barcode: 200028; CIP Link: http://xsjbrdwin1/CIP-E/Component/Index/All?pn=200028; OWNER: 10460; PRICE: 0; Part Type: SMT - 1%; PartType: SMT - 1%; Power: 1/10W; ROHS: Yes; Rated Power: 1/16W; Tolerance: 1%; primarykey: 97
R475 R499 R504 R869 R889 = RES_OHMITE_LVK25: Res 5mR 1% 2W 100PPM 1224 Wide 4-Term; Agile Part Number: RES-00118-01; Barcode: 200097; CIP Link: http://xsjbrdwin1/CIP-E/Component/Index/All?pn=200097; OWNER: 3709; PRICE: 0.89; Part Type: SMT -CURSNS; PartType: SMT -CURSNS; Power: 2W; ROHS: Yes; Rated Power: 2W; Tolerance: 1%; primarykey: 29
R859 R865 = RES: Res 34K8 1% 1/16W 100PPM 50V 0402; ALT_SYMBOLS: RESC100X50X40RND; Agile Part Number: RES-00235-01; Barcode: 200251; CIP Link: http://xsjbrdwin1/CIP-E/Component/Index/All?pn=200251; Part Type: SMT - 1%; Rated Power: 1/10W; Tolerance: 1%
R861 = RES: Res 2K21 1% 1/16W 100PPM 50V 0402; ALT_SYMBOLS: (0402,C402-25,RESC100X50X40L25NRND); Agile Part Number: RES-00023-01; Barcode: 200163; CIP Link: http://xsjbrdwin1/CIP-E/Component/Index/All?pn=200163; Part Type: SMT - 1%; Rated Power: 1/16W; Tolerance: 1%
R862 = RES: RES SMD 3.24K OHM 1% 1/10W 0402; Agile Part Number: RES-00234-01; Barcode: 200250; CIP Link: http://xsjbrdwin1/CIP-E/Component/Index/All?pn=200250; Part Type: SMT - 1%; Rated Power: 1/10W; Tolerance: 1%
R863 = RES: Res 2K 1% 1/16W 100PPM 50V 0402; ALT_SYMBOLS: RESC100X50X40RND; Agile Part Number: RES-00003-01; Barcode: 200096; CIP Link: http://xsjbrdwin1/CIP-E/Component/Index/All?pn=200096; Part Type: SMT - 1%; Rated Power: 1/16W; Tolerance: 1%
R864 = RES: Res 3K65 1% 1/16W 100PPM 50V 0402; Agile Part Number: RES-00255-01; Barcode: 200273; CIP Link: http://xsjbrdwin1/CIP-E/Component/Index/All?pn=200273; Part Type: SMT - 1%; Rated Power: 1/16W; Tolerance: 1%
R1057-R1060 = RES: RES SMD 0 OHM JUMPER 1/8W 2016 Metric Inductor Footprint; Agile Part Number: RES-00116-01; Barcode: 20000023; CIP Link: http://xsjbrdwin1/CIP-E/Component/Index/All?pn=20000023; Part Type: SMT - 5%; Rated Power: 1/8W; Tolerance: 5%
R1095 R1096 = RES: Res 100mR 1% 1/4W 75PPM 0805; Agile Part Number: RES-00502-01; Barcode: 20000017; CIP Link: http://xsjbrdwin1/CIP-E/Component/Index/All?pn=20000017; Part Type: Unassigned Part Type; Rated Power: 0.25W, 1/4W; Tolerance: 1%
R1100 R1103-R1105 = RES: Res 0R 50mR 500mA 0201; ALT_SYMBOLS: RESC60X30X26RND; ASSEMBLY_OPTIONS: DNP; Agile Part Number: RES-00347-01; Barcode: 200383; CIP Link: http://xsjbrdwin1/CIP-E/Component/Index/All?pn=200383; Part Type: SMT - JUMPER; Rated Power: 1/20W; Tolerance: NA
R1101 R1102 R1106 R1107 = RES: Res 0R 50mR 500mA 0201; ALT_SYMBOLS: RESC60X30X26RND; Agile Part Number: RES-00347-01; Barcode: 200383; CIP Link: http://xsjbrdwin1/CIP-E/Component/Index/All?pn=200383; Part Type: SMT - JUMPER; Rated Power: 1/20W; Tolerance: NA
R1750 = RES: Res 845R 1% 1/16W 100PPM 50V 0402; Agile Part Number: RES-00313-01; Barcode: 200347; CIP Link: http://xsjbrdwin1/CIP-E/Component/Index/All?pn=200347; Part Type: SMT - 1%; Rated Power: 1/16W; Tolerance: 1%
U57-U64 U71 U75 U77 U124 = INA226: IC Power Mon I2C 36Vin 5V VSSOP-10; Agile Part Number: ICS-00186-01; Barcode: 500247; CIP Link: http://xsjbrdwin1/CIP-E/Component/Index/All?pn=500247; Family: OPAMP; Part Type: OPAMP; ROHS: Yes
U115 U116 = MPM3683-7: IC V. Reg Step-Down DC/DC 16V 8A 1MHz QFN-28; Agile Part Number: ICS-00506-01; Barcode: 50000039; CIP Link: http://xsjbrdwin1/CIP-E/Component/Index/All?pn=50000039; Part Type: Switching Voltage Regulators\--
U413 = AND_GATE_SINGLE: IC AND Single 2-In 5V 50mA 3.6nSec SC70-5; Agile Part Number: ICS-00094-01; Barcode: 500077; CIP Link: http://xsjbrdwin1/CIP-E/Component/Index/All?pn=500077; Part Type: LOGIC
R413 R422 R424 R425 R429 R466 = RES: Res 10K 1% 1/16W 100PPM 50V 0402; ALT_SYMBOLS: RESC100X50X40RND; Agile Part Number: RES-00030-01; Barcode: 200025; CIP Link: http://xsjbrdwin1/CIP-E/Component/Index/All?pn=200025; OWNER: 4001; PRICE: 0; Part Type: SMT - 1%; PartType: SMT - 1%; Power: 1/10W; ROHS: Yes; Rated Power: 1/16W; Tolerance: 1%; primarykey: 1
R857 R891 = RES: Res 73K2 1% 1/16W 100PPM 50V 0402; Agile Part Number: RES-00157-01; Barcode: 200159; CIP Link: http://xsjbrdwin1/CIP-E/Component/Index/All?pn=200159; Part Type: SMT - 1%; Rated Power: 1/16W; Tolerance: 1%
R858 R890 = RES: Res 150K 5% 1/16W 200PPM 50V 0402; Agile Part Number: RES-00409-01; Barcode: 200467; CIP Link: http://xsjbrdwin1/CIP-E/Component/Index/All?pn=200467; Part Type: SMT - 1%; Rated Power: 1/16W; Tolerance: 1%
U114 U118 U125 = MPM3833C: IC V. Reg Step-Down DC/DC 6V 3A 1.15MHz QFN-18; Agile Part Number: ICS-00505-01; Barcode: 50000040; CIP Link: http://xsjbrdwin1/CIP-E/Component/Index/All?pn=50000040; Part Type: Power Supplies - Board Mount\--
Q36 = FET-3PIN: MOSFET N-Ch 20V 1.3A 160mR SSOT-3; Agile Part Number: TRN-00012-01; Barcode: 500100; CIP Link: http://xsjbrdwin1/CIP-E/Component/Index/All?pn=500100; OWNER: 4001; PRICE: 0.12; Part Type: FET; PartType: FET; Power: 460MW; ROHS: Yes; Rated Power: 460MW; Rated Voltage: 20V
R870 = RES: Res 200K 1% 1/16W 100PPM 50V 0402; Agile Part Number: RES-00078-01; Barcode: 200041; CIP Link: http://xsjbrdwin1/CIP-E/Component/Index/All?pn=200041; Part Type: SMT - 1%; Rated Power: 1/10W; Tolerance: 1%
R871 = RES: Res 49K9 1% 1/16W 100PPM 50V 0402; ALT_SYMBOLS: RESC100X50X40RND; Agile Part Number: RES-00390-01; Barcode: 200433; CIP Link: http://xsjbrdwin1/CIP-E/Component/Index/All?pn=200433; Part Type: SMT - 1%; Rated Power: 1/16W; Tolerance: 1%
R872 = RES: Res 13K3 1% 1/16W 100PPM 50V 0402; Agile Part Number: RES-00389-01; Barcode: 200431; CIP Link: http://xsjbrdwin1/CIP-E/Component/Index/All?pn=200431; Part Type: SMT - 1%; Rated Power: 1/16W; Tolerance: 1%

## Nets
AGND_ADC_AVCC: C1351.2 U115.18(AGND_1) U115.21(AGND_2) Z49.1(NET1)
AGND_DAC_AVCC: C1394.2 U116.18(AGND_1) U116.21(AGND_2) Z51.1(NET1)
AGND_VCC1V8: R873.1 R880.2 R886.2 U123.13(LGnd) Z56.1(NET1)
GND: C521.2 C522.2 C525.2 C527.2 C529.2 C530.2 C533.2 C534.2 C586.2 C589.2 C590.2 C591.2 C593.2 C598.2 C599.2 C626.2 C628.2 C631.2 C633.2 C1344.2 C1345.2 C1346.2 C1347.2 C1349.2 C1350.2 C1354.2 C1355.2 C1358.2 C1359.2 C1360.2 C1361.2 C1362.2 C1363.2 C1364.2 C1365.2 C1366.2 C1367.2 C1368.2 C1369.2 C1370.2 C1371.2 C1372.2 C1373.2 C1374.2 C1375.2 C1377.2 C1378.2 C1380.2 C1381.2 C1382.2 C1383.2 C1384.2 C1385.2 C1386.2 C1387.2 C1388.2 C1389.2 C1390.2 C1393.2 C1397.2 C1398.2 C1399.2 C1400.2 C1401.2 C1402.2 C1403.2 C1404.2 C1405.2 C1407.2 C1408.2 C1409.2 C1410.2 C1411.2 C1413.2 C1414.2 C1415.2 C1416.2 C1417.2 C1418.2 C1419.2 C1420.2 C1421.2 C1425.2 C1426.2 C1427.2 C1428.2 C1429.2 C1430.2 C1431.2 C1432.2 C1433.2 C1434.2 C1435.2 C1437.2 C1438.2 C1439.2 C1440.2 C1441.2 C1442.2 C1443.2 C1444.2 C1445.2 C1446.2 C1596.2 C1798.2 C1799.2 C1800.2 C1801.2 C1954.2 C1955.2 Q36.2(SOURCE) R857.2 R859.2 R860.2 R865.2 R866.2 R872.2 R885.2 R891.2 R1026.2 R1100.2 R1102.2 R1104.2 R1107.2 U57.1(A1) U57.7(GND) U58.1(A1) U58.7(GND) U59.7(GND) U60.1(A1) U60.7(GND) U61.7(GND) U62.7(GND) U63.7(GND) U64.2(A0) U64.7(GND) U71.7(GND) U75.2(A0) U75.7(GND) U77.7(GND) U114.1(AGND) U114.16(PGND) U115.10-11(PGND_1) U115.12(PGND_2) U116.10-11(PGND_1) U116.12(PGND_2) U118.1(AGND) U118.16(PGND) U123.12_25(PGnd) U124.7(GND) U125.1(AGND) U125.16(PGND) U413.3(GND) Z49.2(NET2) Z51.2(NET2) Z55.1(NET1) Z56.2(NET2) ; also on sheet 3 4 5 7 8 9 10 11 12 13 14 16 17 18 19 20 21 22 23 24 25 26 27 28 32 33 34 35 36 37 38 39 40 41 42 43 44 45 46 47 48 49 50 51 57 58 59 60 61 62 63 64 65 66 67 68 69 70 71 72
VCC1V2_SNS_P: U58.8(VBUS) ; also on sheet 47 48
VCC1V2_VIN_R_N: R412.2 ; also on sheet 48
VCC1V2_VIN_R_P: R415.2 ; also on sheet 48
VCC1V8: J115.1(P1) R879.1(R1) Z54.1(NET1) ; also on sheet 3 5 9 10 15 16 17 69
VCC1V8_BUS: C1426.1 C1427.1 C1428.1 C1429.1 C1430.1 C1431.1 C1432.1 C1433.1 C1434.1 L52.2 R879.2(R2) R1026.1 ; also on sheet 4 9 10 12 20 21 22 23 24 25 26 27 34 36 37 38 39 42 61 62 64
VCC1V8_PGOOD: U123.11(PGood) ; also on sheet 34 49 60
VCC1V8_SNS_N: R883.2 R884.2 R885.1 Z55.2(NET2)
VCC1V8_SNS_P: R881.2 R882.2 U60.8(VBUS) Z54.2(NET2)
VCC1V8_SWITCH: C1424.2 L52.1 U123.24(SW)
VCC1V8_VIN_R_N: R418.2 R879.S1
VCC1V8_VIN_R_P: R419.2 R879.S2
VCC1V8_VSNS: R881.1 R886.1 U123.5(Vsns)
VCC12_SW: C1413.1 C1414.1 C1415.1 C1416.1 C1417.1 C1418.1 C1419.1 C1420.1 C1421.1 U123.1(PVin) U123.21(Vin) ; also on sheet 28 31 43 44 45 47 48 49 50 51 57 58 62
VCCINT_AMS_PGOOD: U114.4(EN_1) U413.2(B) ; also on sheet 44 60
VCCINT_AMS_SEN_P: U61.8(VBUS) ; also on sheet 44
VCCINT_AMS_VIN_R_N: R420.2 ; also on sheet 45
VCCINT_AMS_VIN_R_P: R423.2 ; also on sheet 45
VCCINT_IO_BRAM_PS_SNS_P: U57.8(VBUS) ; also on sheet 50
VCCINT_IO_BRAM_PS_VIN_R_N: R411.2 ; also on sheet 50
VCCINT_IO_BRAM_PS_VIN_R_P: R414.2 ; also on sheet 50
ADC_AVCC: J78.1(P1) R499.I1 R1106.2 ; also on sheet 13 70
ADC_AVCC_BUS: C1358.1 C1359.1 C1360.1 C1361.1 C1362.1 C1363.1 C1364.1 C1365.1 C1366.1 C1367.1 C1368.1 C1369.1 C1370.1 C1798.1 C1799.1 R499.I2 R1057.2 R1058.2 R1095.1
ADC_AVCC_EN: U115.3(EN) U413.4(Y)
ADC_AVCC_PGOOD: U115.4(PG) ; also on sheet 60
ADC_AVCC_SNS_N: C1352.2 C1356.2 J148.2(P2) R1104.1 R1107.1 R1750.2 U115.25(VoSense-)
ADC_AVCC_SNS_P: C1353.2 R861.2 R1105.2 R1106.1 U75.8(VBUS)
ADC_AVCC_VIN_R_N: R498.2 R499.V1
ADC_AVCC_VIN_R_P: R497.2 R499.V2
ADC_AVCCAUX: J75.1(P1) R475.I1 Z48.1(NET1) ; also on sheet 13 70
ADC_AVCCAUX_BUS: C589.1 C590.1 C591.1 C593.1 C598.1 C599.1 C1347.1 C1408.1 R475.I2 R858.1 U114.3(OUT_S) U114.8-10(OUT)
ADC_AVCCAUX_PGOOD: U114.12(PG) U116.3(EN) U118.4(EN_1) U125.4(EN_1) U413.1(A) ; also on sheet 60
ADC_AVCCAUX_SNS: U71.8(VBUS) Z48.2(NET2)
ADC_AVCCAUX_VIN_R_N: R468.2 R475.V1
ADC_AVCCAUX_VIN_R_P: R467.2 R475.V2
DAC_AVCC: J79.1(P1) R504.I1 R1101.2 ; also on sheet 14 70
DAC_AVCC_BUS: C1377.1 C1378.1 C1380.1 C1381.1 C1382.1 C1383.1 C1384.1 C1385.1 C1386.1 C1387.1 C1388.1 C1389.1 C1390.1 C1800.1 C1801.1 R504.I2 R1059.2 R1060.2 R1096.1
DAC_AVCC_PGOOD: U116.4(PG) ; also on sheet 60
DAC_AVCC_SNS_N: C1391.2 C1392.2 R864.2 R1100.1 R1102.1 U116.25(VoSense-)
DAC_AVCC_SNS_P: C1379.2 R863.1 R1101.1 R1103.2 U77.8(VBUS)
DAC_AVCC_VIN_R_N: R503.2 R504.V1
DAC_AVCC_VIN_R_P: R502.2 R504.V2
DAC_AVCCAUX: J116.1(P1) R889.I1 Z57.1(NET1) ; also on sheet 14 70
DAC_AVCCAUX_BUS: C1410.1 C1440.1 C1441.1 C1442.1 C1443.1 C1444.1 C1445.1 C1446.1 R889.I2 R890.1 U125.3(OUT_S) U125.8-10(OUT)
DAC_AVCCAUX_PGOOD: U125.12(PG) ; also on sheet 60
DAC_AVCCAUX_SNS: U124.8(VBUS) Z57.2(NET2)
DAC_AVCCAUX_VIN_R_N: R888.2 R889.V1
DAC_AVCCAUX_VIN_R_P: R887.2 R889.V2
DAC_AVTT: J113.1(P1) R869.I1 Z53.1(NET1) ; also on sheet 14 70
DAC_AVTT_BUS: C1400.1 C1401.1 C1402.1 C1403.1 C1404.1 C1405.1 C1407.1 C1409.1 R869.I2 R870.1 U118.3(OUT_S) U118.8-10(OUT) ; also on sheet 62
DAC_AVTT_PGOOD: U118.12(PG) ; also on sheet 60
DAC_AVTT_SNS_P: U59.8(VBUS) Z53.2(NET2)
DAC_AVTT_VIN_R_N: R416.2 R869.V1
DAC_AVTT_VIN_R_P: R417.2 R869.V2
DAC_AVTT_VOUT_SEL: Q36.1(GATE) ; also on sheet 22
INA226_PMBUS_ALERT: U57.3(ALERT) U58.3(ALERT) U59.3(ALERT) U60.3(ALERT) U61.3(ALERT) U62.3(ALERT) U63.3(ALERT) U64.3(ALERT) U71.3(ALERT) U75.3(ALERT) U77.3(ALERT) U124.3(ALERT) ; also on sheet 22 45 51
INA226_PMBUS_SCL: U57.5(SCL) U58.2(A0) U58.5(SCL) U59.5(SCL) U60.5(SCL) U61.5(SCL) U62.5(SCL) U63.2(A0) U63.5(SCL) U64.5(SCL) U71.1(A1) U71.5(SCL) U75.1(A1) U75.5(SCL) U77.1(A1) U77.5(SCL) U124.2(A0) U124.5(SCL) ; also on sheet 22 45 51
INA226_PMBUS_SDA: U57.4(SDA) U58.4(SDA) U59.1(A1) U59.2(A0) U59.4(SDA) U60.2(A0) U60.4(SDA) U61.1(A1) U61.4(SDA) U62.4(SDA) U63.4(SDA) U64.1(A1) U64.4(SDA) U71.4(SDA) U75.4(SDA) U77.2(A0) U77.4(SDA) U124.1(A1) U124.4(SDA) ; also on sheet 22 45 51
IRPS5401_ALERT_B: U123.17(SAlert#) ; also on sheet 22 44 47 49 50 51
IRPS5401_SCL: U123.19(SCL) ; also on sheet 22 44 47 49 50 51
IRPS5401_SDA: U123.18(SDA) ; also on sheet 22 44 47 49 50 51
MGT1V2_SNS_P: U63.8(VBUS) ; also on sheet 49
MGT1V2_VIN_R_N: R427.2 ; also on sheet 49
MGT1V2_VIN_R_P: R430.2 ; also on sheet 49
MGT1V8_SNS_P: U64.8(VBUS) ; also on sheet 47
MGT1V8_VIN_R_N: R428.2 ; also on sheet 47
MGT1V8_VIN_R_P: R431.2 ; also on sheet 47
UTIL_3V3: C521.1 C522.1 C525.1 C527.1 C529.1 C530.1 C533.1 C534.1 C586.1 C626.1 C633.1 C1435.1 C1596.1 R413.1 R422.1 R424.1 R425.1 R429.1 R466.1 U57.6(VS_P) U58.6(VS_P) U59.6(VS_P) U60.6(VS_P) U61.6(VS_P) U62.6(VS_P) U63.6(VS_P) U64.6(VS_P) U71.6(VS_P) U75.6(VS_P) U77.6(VS_P) U124.6(VS_P) U413.5(VCC) ; also on sheet 9 10 20 22 23 24 25 26 27 28 29 30 31 33 34 36 37 40 42 43 44 45 47 49 51 57 59 60 61 64
UTIL_5V0: C628.1 C1344.1 C1345.1 C1346.1 C1349.1 C1350.1 C1371.1 C1372.1 C1373.1 C1397.1 C1398.1 C1399.1 C1437.1 C1438.1 C1439.1 U114.13(VIN_1) U114.14(VIN_2) U115.5(VIN_1) U115.8(VIN_2) U115.9(VIN_3) U115.27(VIN_4) U116.5(VIN_1) U116.8(VIN_2) U116.9(VIN_3) U116.27(VIN_4) U118.13(VIN_1) U118.14(VIN_2) U125.13(VIN_1) U125.14(VIN_2) ; also on sheet 20 44 45 48 58 60 62 64 71 72
UTIL_5V0_PGOOD: U123.3(EN/FCCM) ; also on sheet 47 48 49 50 51 58 60
VADJ_FMC_SNS_P: U62.8(VBUS) ; also on sheet 47
VADJ_FMC_VIN_R_N: R421.2 ; also on sheet 47
VADJ_FMC_VIN_R_P: R426.2 ; also on sheet 47
N18154761: C524.1 R411.1 U57.9(VIN_N)
N18154765: C524.2 R414.1 U57.10(VIN_P)
N18155227: C528.2 R419.1 U60.10(VIN_P)
N18155231: C528.1 R418.1 U60.9(VIN_N)
N18155500: C531.1 R420.1 U61.9(VIN_N)
N18155502: C531.2 R423.1 U61.10(VIN_P)
N18155813: C536.2 R430.1 U63.10(VIN_P)
N18155817: C536.1 R427.1 U63.9(VIN_N)
N18155887: R429.2 U63.1(A1)
N18156695: C523.2 R415.1 U58.10(VIN_P)
N18156699: C523.1 R412.1 U58.9(VIN_N)
N18157325: C532.2 R426.1 U62.10(VIN_P)
N18157329: C532.1 R421.1 U62.9(VIN_N)
N18157406: R425.2 U62.1(A1)
N18157934: R413.2 U57.2(A0)
N18158787: R424.2 U62.2(A0)
N18159210: C535.2 R431.1 U64.10(VIN_P)
N18159228: C535.1 R428.1 U64.9(VIN_N)
N18159940: R422.2 U61.2(A0)
N18160539: C587.2 R467.1 U71.10(VIN_P)
N18160541: C587.1 R468.1 U71.9(VIN_N)
N18160623: R466.2 U71.2(A0)
N18162252: C634.1 R503.1 U77.9(VIN_N)
N18162254: C634.2 R502.1 U77.10(VIN_P)
N18163783: C627.2 R497.1 U75.10(VIN_P)
N18163785: C627.1 R498.1 U75.9(VIN_N)
N19722924: C526.2 R417.1 U59.10(VIN_P)
N19722926: C526.1 R416.1 U59.9(VIN_N)
N24237021: C1424.1 R878.2
N24237084: R878.1 U123.2(Boot)
N24237089: R882.1 R883.1 U123.10(RS+)
N24237095: R884.1 U123.9(RS-)
N24237118: R873.2 U123.4(ADDR)
N24237124: C1411.1 U123.22(Vcc)
N24237127: C1425.1 U123.20(P1V8)
N24237129: R876.2 U123.8(RSo)
N24237130: C1412.2 R875.2 R876.1
N24237131: C1412.1 R874.2
N24237135: C1422.1 R874.1 R875.1 R877.1 R880.1 U123.6(FB)
N24237140: C1422.2 C1423.2 U123.7(Comp)
N24237144: C1423.1 R877.2
N24242361: R857.1 R858.2 U114.2(FB)
N24244890: R890.2 R891.1 U125.2(FB)
N24246225: C1436.1 R888.1 U124.9(VIN_N)
N24246247: C1436.2 R887.1 U124.10(VIN_P)
N24246905: C631.1 U115.13(VCC)
N24246957: R859.1 U115.23(MODE)
N24247119: R860.1 U115.22(CS)
N24248484: C1351.1 C1352.1 U115.24(REF/TRK)
N24249118: C1353.1 C1356.1 R861.1 R862.1 U115.26(VoSense+)
N24249546: C1354.1 C1355.1 R1057.1 R1058.1 R1105.1 U115.1-2(VOUT_1) U115.6-7(VOUT_2)
N24254431: C1374.1 C1375.1 R1059.1 R1060.1 R1103.1 U116.1-2(VOUT_1) U116.6-7(VOUT_2)
N24254585: C1379.1 C1392.1 R863.2 R864.1 U116.26(VoSense+)
N24254611: C1393.1 U116.13(VCC)
N24254875: R865.1 U116.23(MODE)
N24254908: C1391.1 C1394.1 U116.24(REF/TRK)
N24254928: R866.1 U116.22(CS)
N24257510: R870.2 R871.1 U118.2(FB)
N26785871: Q36.3(DRAIN) R871.2 R872.1
N27633134: C1954.1 R1095.2
N27633226: C1955.1 R1096.2
N31516343: J148.1(P1) R862.2 R1750.1

Not connected (* = marked no-connect by the designer): U114 5-7(SW_1)* 11(NC)* 15(SW_2)* 17(NC1)* 18(NC2)*; U115 14-15(SW_1)* 16(SW_2)* 17(BST)* 19-20(SW_3)* 28(SW_4)*; U116 14-15(SW_1)* 16(SW_2)* 17(BST)* 19-20(SW_3)* 28(SW_4)*; U118 5-7(SW_1)* 11(NC)* 15(SW_2)* 17(NC1)* 18(NC2)*; U123 14(SV_CLK)* 15(SV_DIO)* 16(SV_ALERT)* 23(NC1)* 26(NC2)*; U125 5-7(SW_1)* 11(NC)* 15(SW_2)* 17(NC1)* 18(NC2)*

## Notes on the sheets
sheet 52
- REPLACE IC WITH CORRECT FIRMWARE P/N
- 1.8V @ 8A
- OFFSET: +12
  7-BIT I2C ADDR: 0x1C
  7-BIT PMBUS ADDR: 0x4C
sheet 53
- I2C ADDR
  0x4C
- 0.925V/1.01V
  @ 4A
- Place remote sense
  lines at FPGA
- J148: Open = Fastnet
        Shunt = Maxwell
- I2C ADDR
  0x4E
- Place optional 0201s near U115
- 0.925V @ 6A
- Place remote sense
  lines at FPGA
- Place optional 0201s near U116
sheet 54
- I2C ADDR
  0x4D
- 1.8V @ 2A
sheet 55
- I2C ADDR
  0x4B
- 1.8V @ 1.5A
- 2.5V or 3.0V @ 1.5A
sheet 56
- I2C ADDR
  0x41
- I2C ADDR
  0x43
- I2C ADDR
  0x42
- I2C ADDR
  0x4A
- I2C ADDR
  0x49
- I2C ADDR
  0x45
- I2C ADDR
  0x47
- I2C ADDR
  0x48
